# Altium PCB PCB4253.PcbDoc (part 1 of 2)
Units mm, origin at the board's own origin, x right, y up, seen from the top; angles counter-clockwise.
Board outline 30 x 51 mm, 6 copper layers (Top Layer, Signal Layer 2, GND Layer 3, PWR Layer 4, Signal Layer 5, Bottom Layer), stack 1.656 mm thick; 84 components, 108 nets, 396 pads, 436 vias.
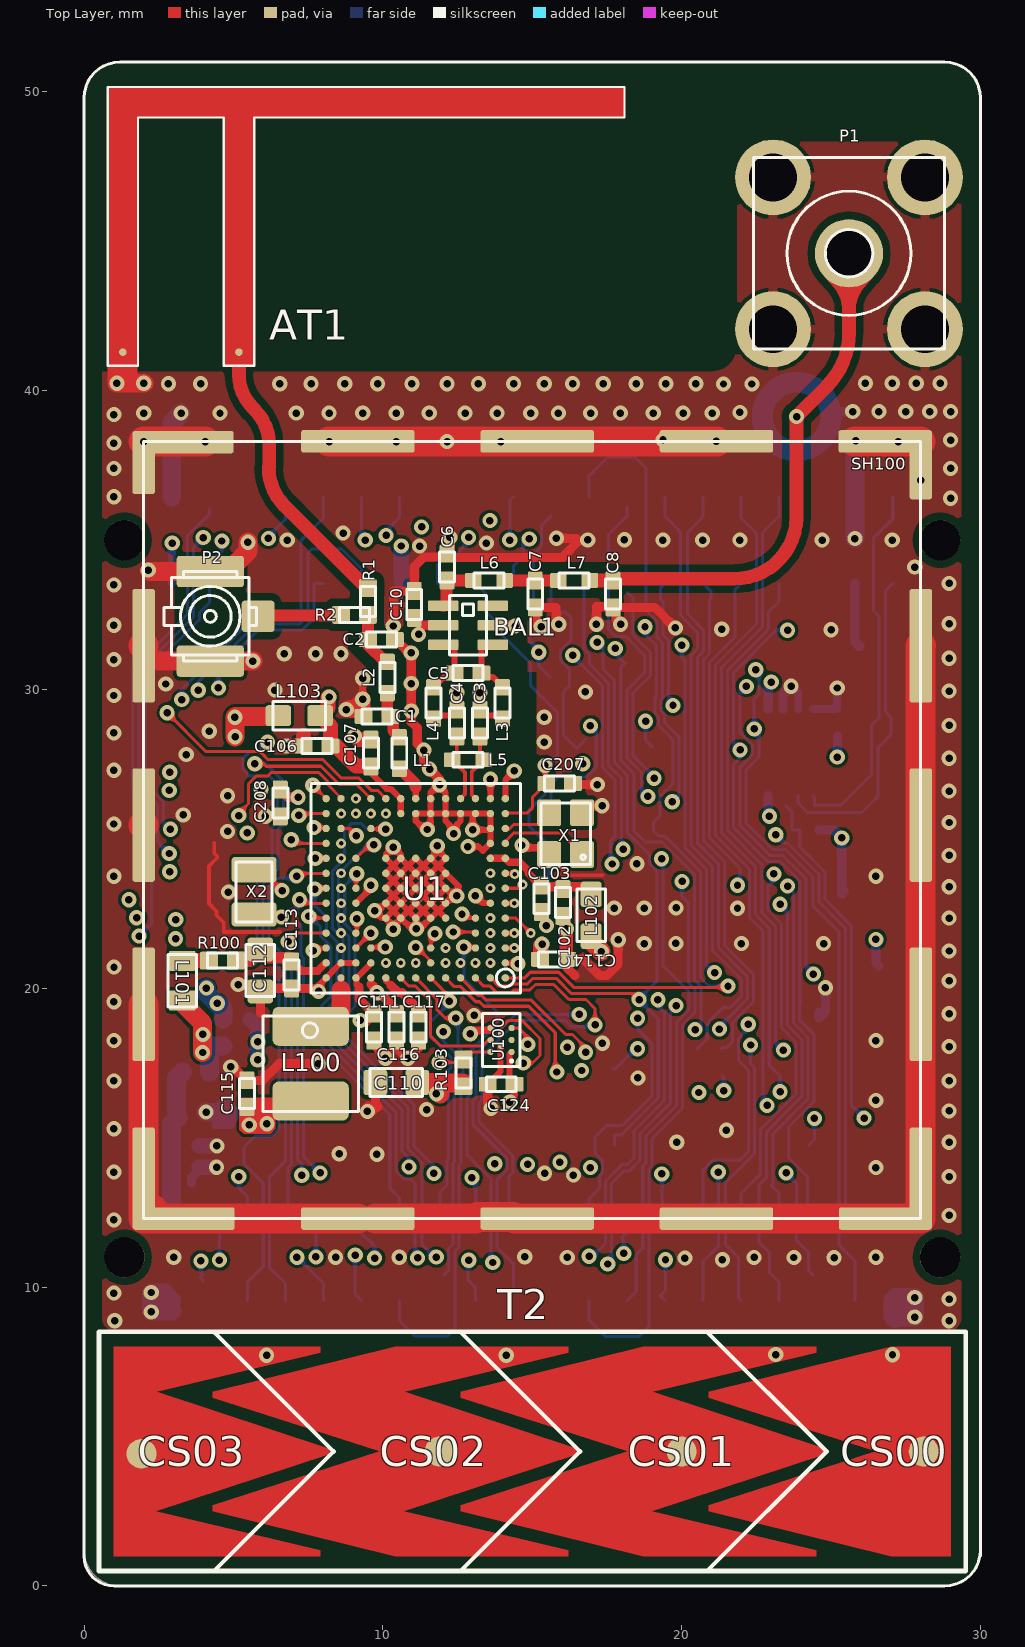
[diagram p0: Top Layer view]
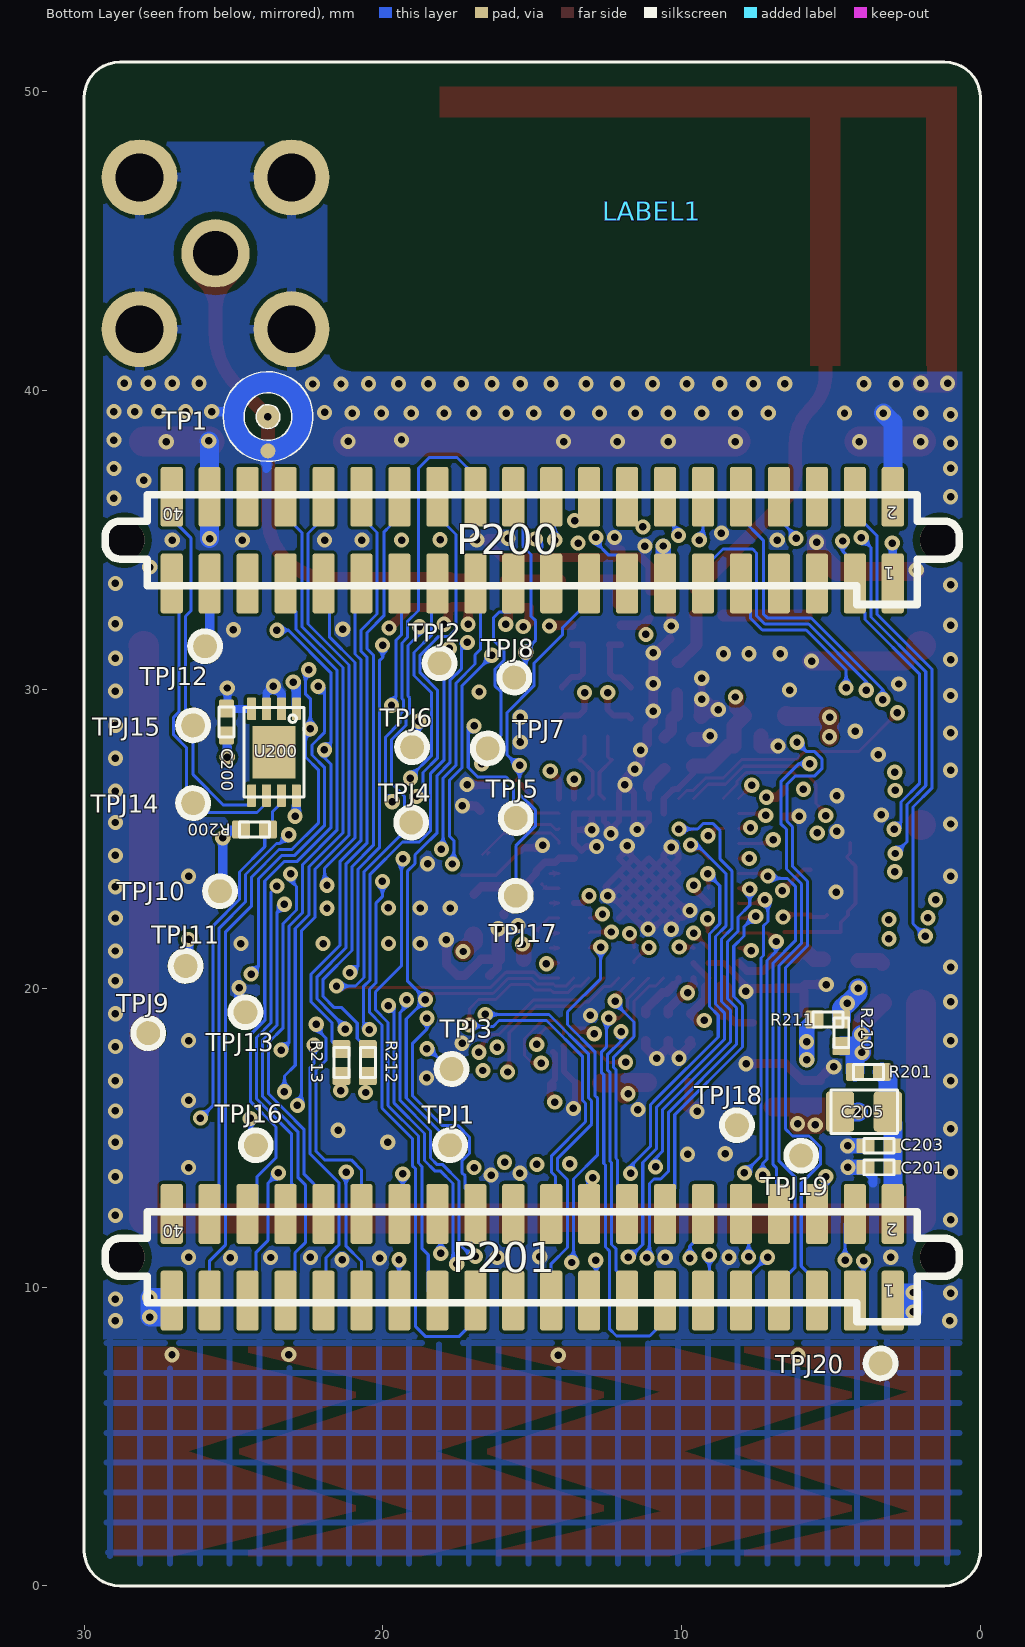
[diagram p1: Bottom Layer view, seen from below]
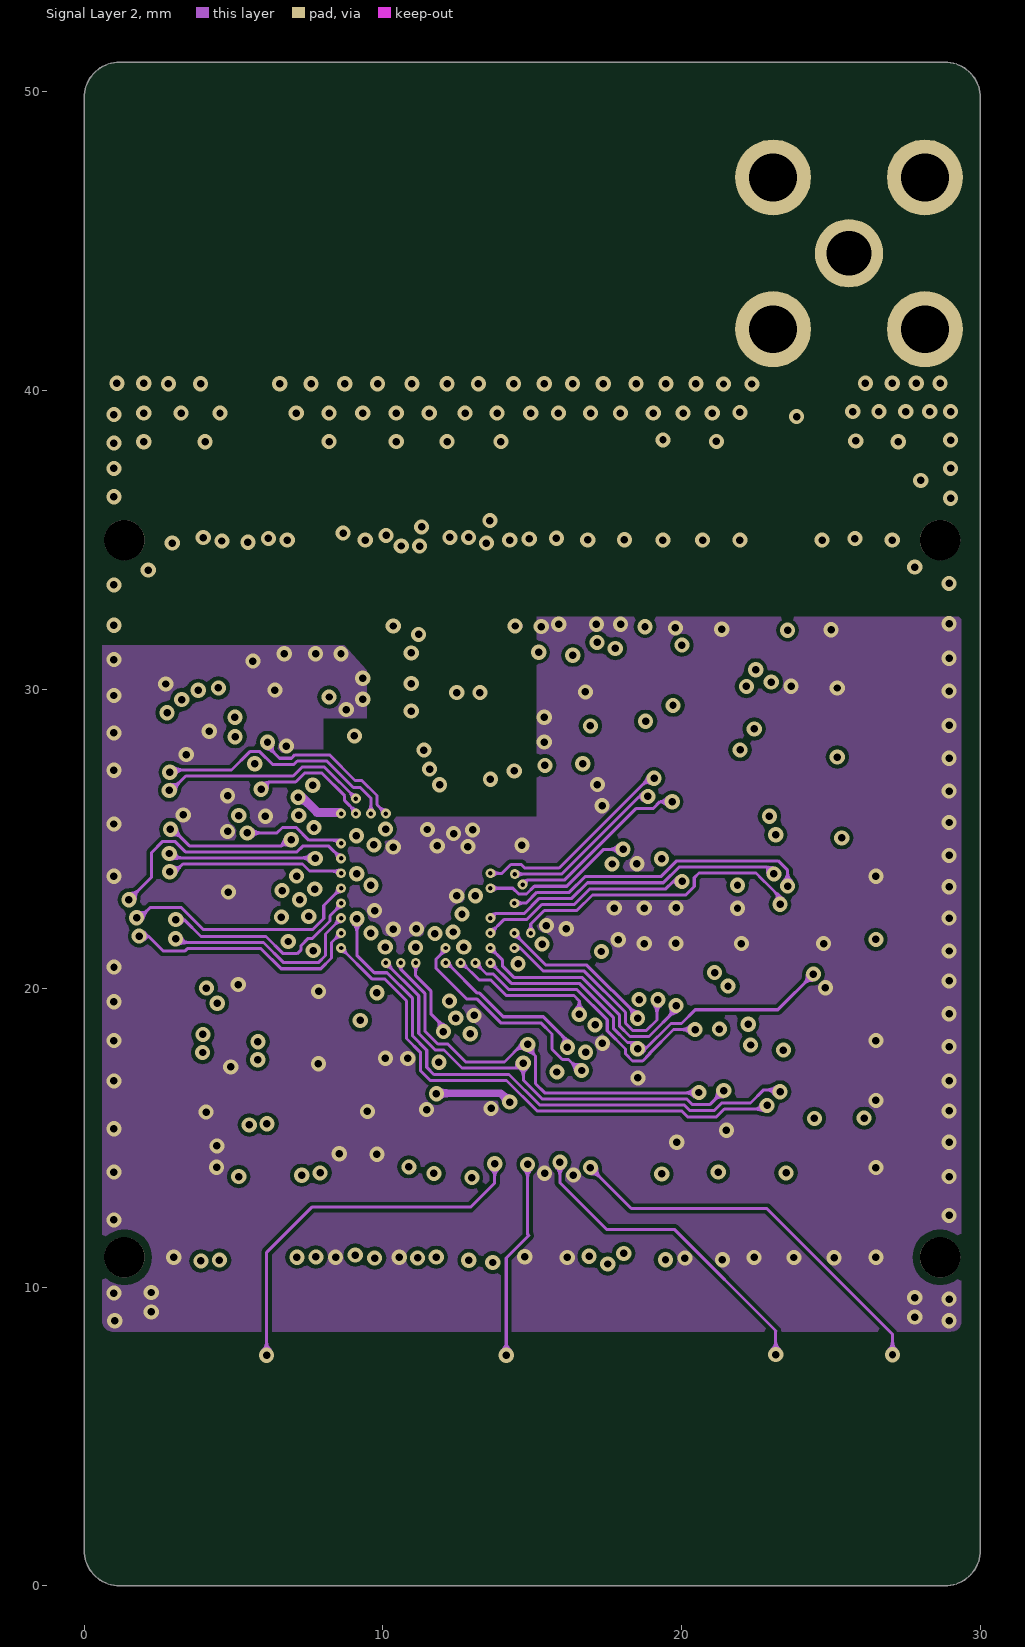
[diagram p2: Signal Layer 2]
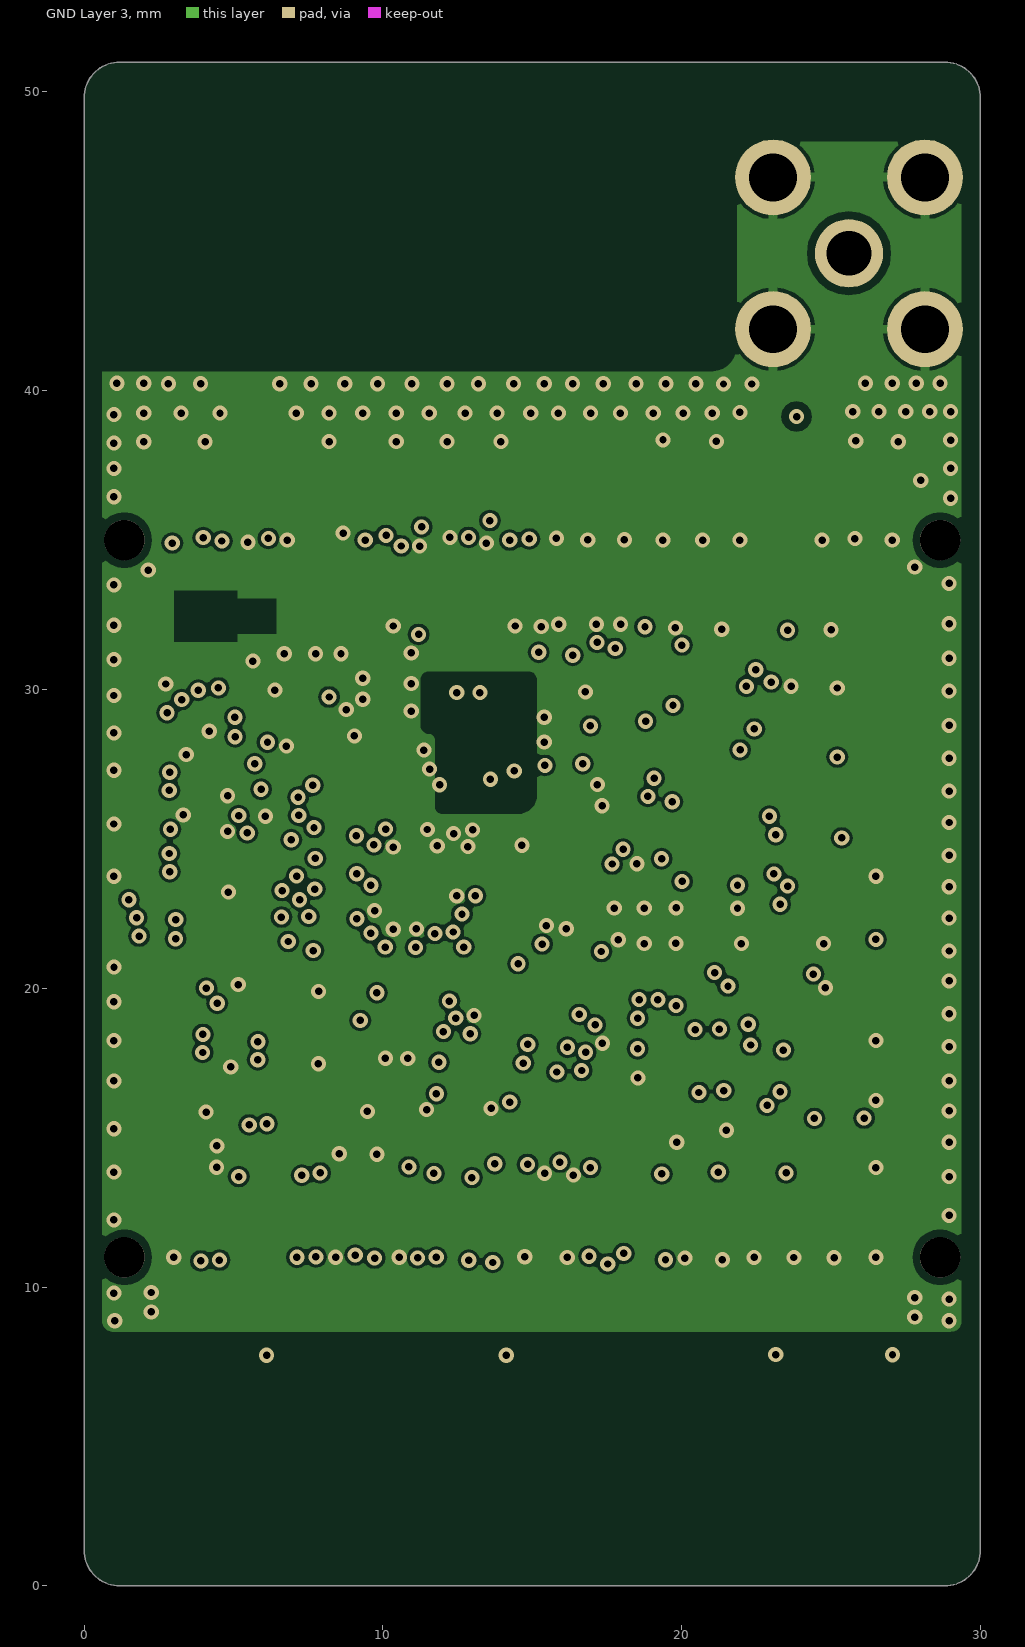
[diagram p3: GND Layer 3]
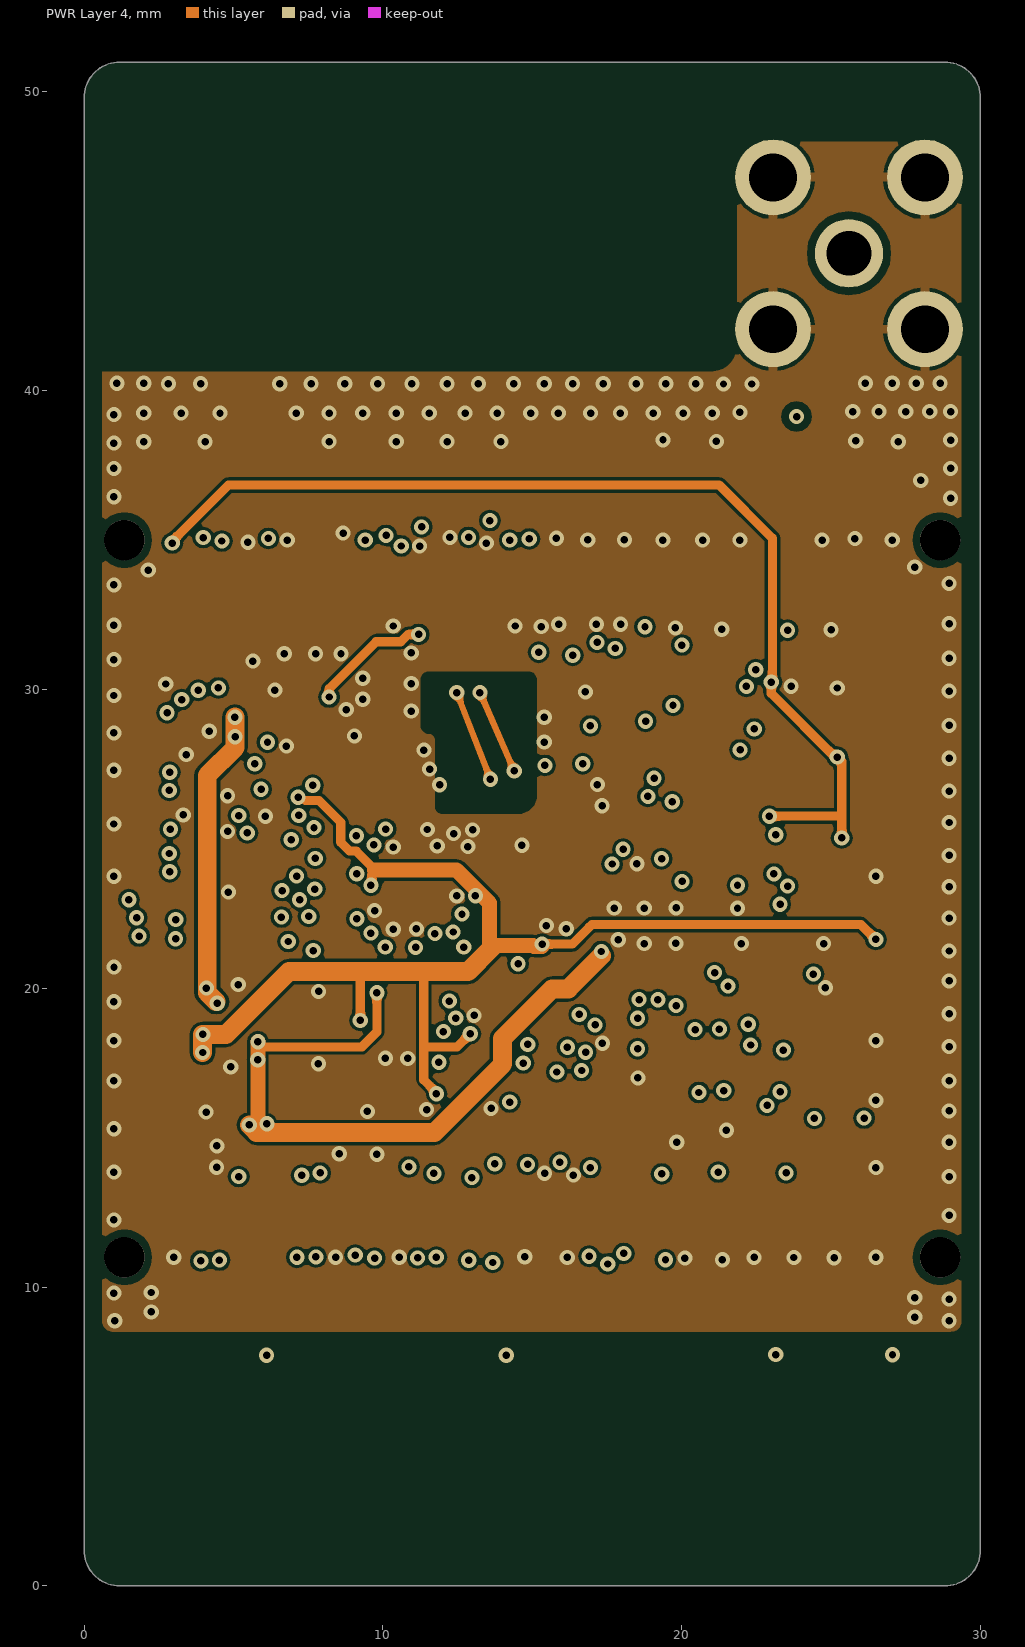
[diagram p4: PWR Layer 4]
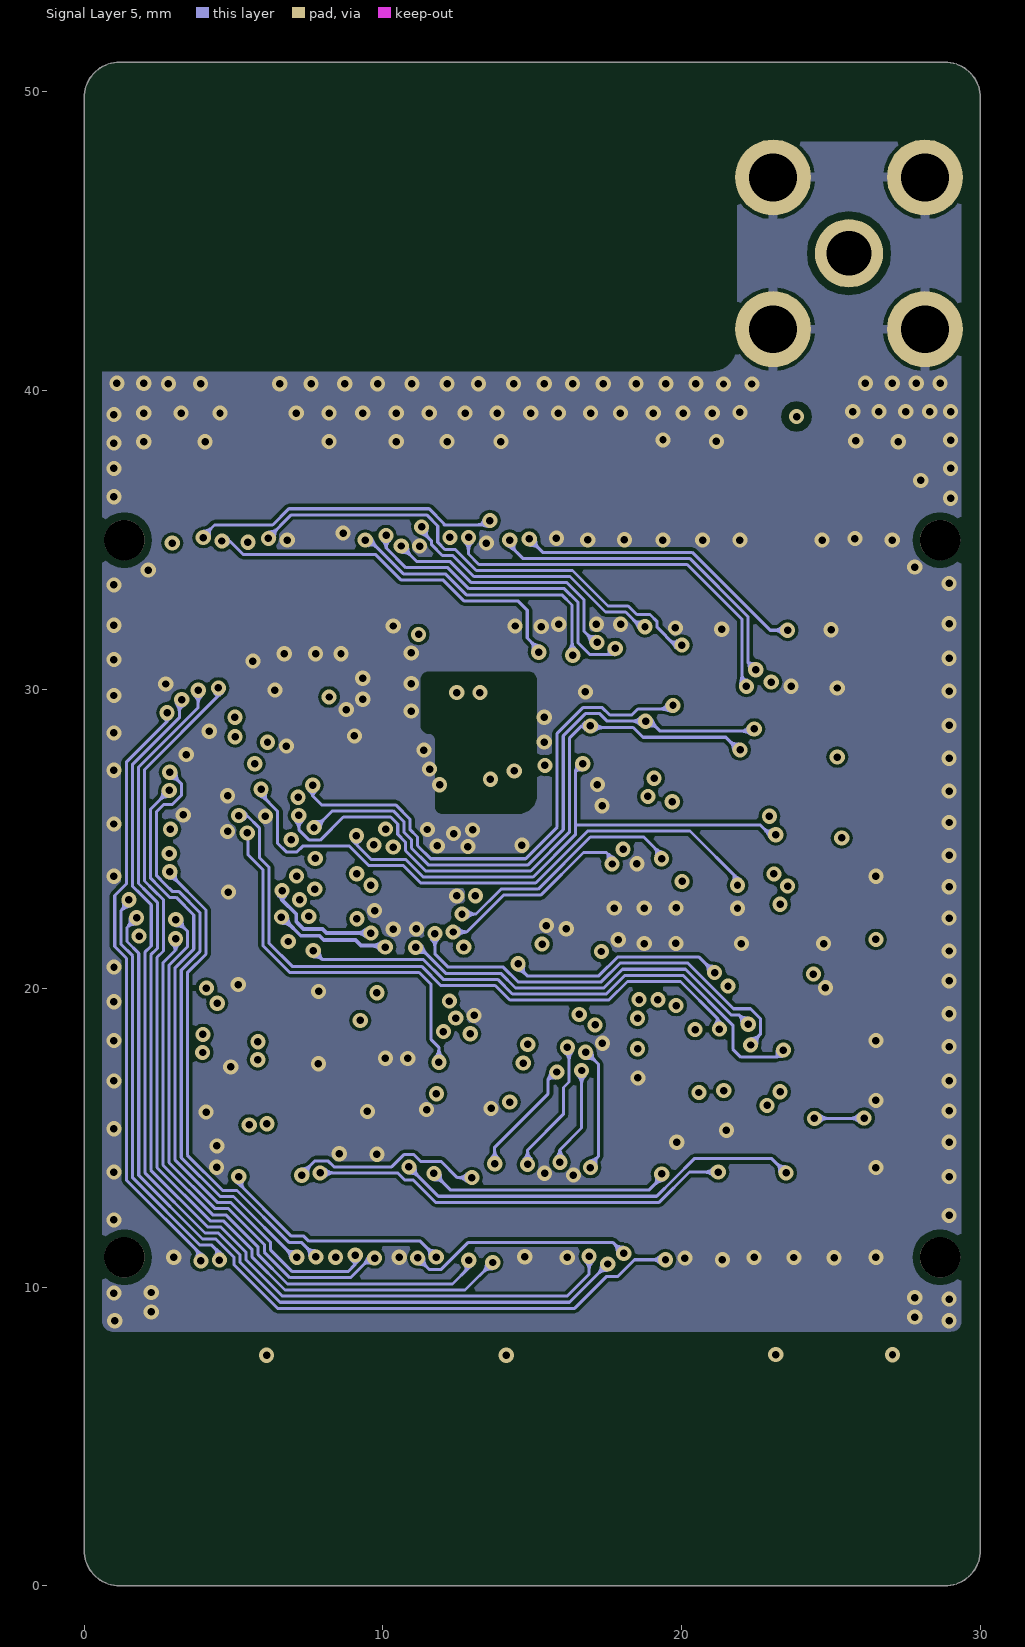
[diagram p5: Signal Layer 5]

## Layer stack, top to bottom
Top Solder: solder mask 0.01, Solder Resist, Dk 3.5
Top Layer: signal copper 0.035
Dielectric 1: prepreg 0.09, FR-4, Dk 4.2
Signal Layer 2: signal copper 0.035
Dielectric 2: core 0.18, Dk 4.2
GND Layer 3: signal copper 0.035
Dielectric 3: prepreg 0.906, FR-4, Dk 4.2
PWR Layer 4: signal copper 0.035
Dielectric 5: core 0.18, Dk 4.2
Signal Layer 5: signal copper 0.035
Dielectric 6: prepreg 0.09, Dk 4.2
Bottom Layer: signal copper 0.035
Bottom Solder: solder mask 0.01, Solder Resist, Dk 3.5

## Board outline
0,1.2 ccw(c1.2,1.2) 1.2,0 28.8,0 ccw(c28.8,1.2) 30,1.2 30,49.8 ccw(c28.8,49.8) 28.8,51 1.2,51 ccw(c1.2,49.8) 0,49.8

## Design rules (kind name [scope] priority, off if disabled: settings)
Clearance Clearance_to_Holes [InPadClass('NPTH')] p1: gap=0.254
Clearance Clearance_NetP2_1 [InNet('NetP2_1')] p2: gap=0.25
Clearance Clearance_NetC8 [InNet('NetC8_1')] p3: gap=0.25
Clearance Clearance_Net_AT1_1 [InNet('NetAT1_1')] p4: gap=0.25
Clearance Clerance_Polygon_GND3 [InNamedPolygon('GND_3')] p5: gap=0.127
Clearance Clerance_Polygon_GND2 [InNamedPolygon('GND_2')] p6: gap=0.127
Clearance Clerance_Polygon_GND1 [InNamedPolygon('GND_L2')] p7: gap=0.127
Clearance Clerance_Polygon_GND4 [InNamedPolygon('GND_4')] p8: gap=0.127
Clearance Clearance_General [All] p9: gap=0.102
HoleToHoleClearance HoleToHoleClearance_ANT1toPAD [Incomponent ('ANT1') vs ISpad] p1: gap=0 allowstackedmicrovias=TRUE
HoleToHoleClearance HoleToHoleClearance_U1toVIA_1 [InComponent ('U1') vs IsVia] p2: gap=0 allowstackedmicrovias=TRUE
HoleToHoleClearance [All] p3: gap=0.254 allowstackedmicrovias=TRUE
MinimumSolderMaskSliver [All] p1: minsoldermaskwidth=0.102
PolygonConnect PolygonConnect_SH100 [InComponent('SH100')] p1: connectstyle=Direct reliefconductorwidth=0.254 reliefentries=4 polygonreliefangle="90 Angle" airgapwidth=0.127
PolygonConnect PolygonConnect_P1 [InComponent('P1')] p2: connectstyle=Relief reliefconductorwidth=0.305 reliefentries=4 polygonreliefangle="90 Angle" airgapwidth=0.127
PolygonConnect Polygon_VIA_Connect [IsVia] p3: connectstyle=Direct reliefconductorwidth=0.254 reliefentries=4 polygonreliefangle="90 Angle" airgapwidth=0.254
PolygonConnect PolygonConnect_General [All] p4: connectstyle=NoConnect reliefconductorwidth=0.254 reliefentries=4 polygonreliefangle="90 Angle" airgapwidth=0.127
RoutingVias [All] p1: holewidth=0.25 width=0.508 viastyle="Through Hole" minholewidth=0.25 minwidth=0.508 maxholewidth=1 maxwidth=1.5
SilkToSilkClearance [All] p1: silktosilkclearance=0.102
SilkToSolderMaskClearance [IsPad] p1: minsilkscreentomaskgap=0.102 clearancetoexposedcopper=TRUE
SolderMaskExpansion [All] p1: expansion=0.051
Width [All] p1: maxlimit=5.08 minlimit=0.102 preferedwidth=0.127
26 further rules are at their usual default settings.

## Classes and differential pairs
pad class NPTH: P200-M1 P200-M2 P201-M1 P201-M2
net class RADIO_PK[2..0]: RADIO_PK0 RADIO_PK1 RADIO_PK2
net class RADIO_PJ[15..14]: RADIO_PJ14 RADIO_PJ15
net class RADIO_PI[3..0]: RADIO_PI0 RADIO_PI1 RADIO_PI2 RADIO_PI3
component class "01_ Title Page": PCB1
component class "02_ RF, Antenna & Power": AT1 BAL1 C1 C2 C3 C4 C5 C6 C7 C8 C10 C102 C103 C106 C107 C110 C111 C112 C113 C114 C115 C116 C117 C208 L1 L2 L3 L4 L5 L6 L7 L100 L101 L102 L103 P1 P2 R1 R2 R100 R210 R211 SH100 TP1 X1 X2
component class "03_ EFR32 Signal Assign": 180 C124 C207 R103 R203 R204 R213 RP200 T2 U1
component class "04_ WSTK Connectors & B": C200 C201 C203 C205 R200 R201 TPJ1 TPJ2 TPJ3 TPJ4 TPJ5 TPJ6 TPJ7 TPJ8 TPJ9 TPJ10 TPJ11 TPJ12 TPJ13 TPJ14 TPJ15 TPJ16 TPJ17 TPJ18 TPJ19 TPJ20 U200
net class RADIO_PA[9..0]: RADIO_PA0 RADIO_PA1 RADIO_PA2 RADIO_PA3 RADIO_PA4 RADIO_PA5 RADIO_PA6 RADIO_PA7 RADIO_PA8 RADIO_PA9
net class RADIO_PB[15..6]: RADIO_PB6 RADIO_PB7 RADIO_PB8 RADIO_PB9 RADIO_PB10 RADIO_PB11 RADIO_PB12 RADIO_PB13 RADIO_PB14 RADIO_PB15
net class RADIO_PC[11..0]: RADIO_PC0 RADIO_PC1 RADIO_PC2 RADIO_PC3 RADIO_PC4 RADIO_PC5 RADIO_PC6 RADIO_PC7 RADIO_PC8 RADIO_PC9 RADIO_PC10 RADIO_PC11
net class RADIO_PD[15..8]: RADIO_PD8 RADIO_PD9 RADIO_PD10 RADIO_PD11 RADIO_PD12 RADIO_PD13 RADIO_PD14 RADIO_PD15
net class RADIO_PF[15..0]: RADIO_PF0 RADIO_PF1 RADIO_PF2 RADIO_PF3 RADIO_PF4 RADIO_PF5 RADIO_PF6 RADIO_PF7 RADIO_PF8 RADIO_PF9 RADIO_PF10 RADIO_PF11 RADIO_PF12 RADIO_PF13 RADIO_PF14 RADIO_PF15
net class WSTK_F[21..0]: WSTK_F4 WSTK_F15 WSTK_F16
net class WSTK_P[45..0]: WSTK_P18 WSTK_P19 WSTK_P32 WSTK_P38 WSTK_P39 WSTK_P40

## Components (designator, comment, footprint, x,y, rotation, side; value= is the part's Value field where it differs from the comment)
AT1 "INVERTED_F" ANT_INV_F_2.4_GHZ_17.3MM_MIR 0.79,40.84 r0 top locked net-tie
BAL1 "0900BL15C050" BALUN_JOH_0900BL15 12.85,32.15 r0 top
C1 "cfg" C0402_L 9.8,29.1 r0 top
C2 "cfg" C0402_L 9.95,31.675 r180 top
C3 "cfg" C0402_L 13.25,28.875 r270 top
C4 "cfg" C0402_L 12.475,28.875 r270 top
C5 "cfg" C0402_L 12.85,30.55 r180 top
C6 "cfg" C0402_L 12.15,34.1 r90 top
C7 "cfg" C0402_L 15.1,33.2 r270 top
C8 "cfg" C0402_L 17.7,33.2 r270 top
C10 "cfg" C0402_L 11.05,32.85 r90 top
C102 "100P" C0402_L 16.03,22.869 r270 top
C103 "10P" C0402_L 15.306,22.998 r270 top
C106 "220N" C0402_L 7.793,28.107 r180 top
C107 "10P" C0402_L 9.6,27.875 r90 top
C110 "10U" C0603_L 10.45,16.85 r180 top
C111 "1U" C0402_L 9.7,18.7 r270 top
C112 "10U" C0603_L 5.9,20.6 r270 top
C113 "10N" C0402_L 6.95,20.45 r270 top
C114 "1U" C0402_L 15.711,20.972 r0 top
C115 "4U7" C0402_L 5.45,16.475 r90 top
C116 "100N" C0402_L 10.45,18.7 r270 top
C117 "1U" C0402_L 11.2,18.7 r270 top
C124 "100N" C0402_L 13.961,16.791 r180 top
C200 "100N" C0402_L 25.232,28.915 r90 bottom
C201 "100N" C0402_L 3.4,14.012 r0 bottom
C203 "100N" C0402_L 3.4,14.732 r0 bottom
C205 "10U" C0805_L 3.9,15.875 r0 bottom
C207 "100N" C0402_L 15.918,26.857 r0 top
C208 "100N" C0402_L 6.569,26.201 r270 top
L1 "cfg" COIL_0402_L 10.55,27.875 r90 top
L2 "cfg" COIL_0402_L 10.15,30.4 r90 top
L3 "cfg" COIL_0402_L 14,29.55 r270 top
L4 "cfg" COIL_0402_L 11.7,29.55 r270 top
L5 "cfg" COIL_0402_L 12.85,27.65 r0 top
L6 "cfg" COIL_0402_L 13.55,33.65 r180 top
L7 "cfg" COIL_0402_L 16.4,33.65 r180 top
L100 "4U7" COIL_MUR_LQH3NP_1212 7.584,17.477 r270 top
L101 "CBF102WB" COIL_WURTH_CBF_0603_L 3.286,20.257 r90 top
L102 "BLM18AG601SN1" COIL_MUR_BLM18_0603 16.972,22.446 r90 top
L103 "BLM18AG601SN1" COIL_MUR_BLM18_0603 7.2,29.125 r0 top
LABEL1 "Comment" LABEL_4CORNERS_19.0X6.0 11,46 r180 bottom
P1 "SMA" TE_SMA_1814832_TH_VER 25.6,44.6 r0 top locked
P2 "U.FL" COAX_HIROSE_U.FL_CL331-0471 4.225,32.45 r270 top
P200 "SOCKET_2X20_1.27MM_SMD" SAM_SFC-120-T2-D-A-2X20_SNUM 15,35 r0 bottom
P201 "SOCKET_2X20_1.27MM_SMD" SAM_SFC-120-T2-D-A-2X20_SNUM 15,11 r0 bottom
R1 "0R" R0402_L 9.5,32.95 r90 top
R2 "0R" R0402_L 9.05,32.5 r180 top
R100 "1R" R0402_L 4.631,20.926 r0 top
R103 "330K" R0402_L 12.695,17.172 r90 top
R200 "10K" R0402_L 24.295,25.314 r0 bottom
R201 "0R" R0402_L 3.75,17.2 r0 bottom
R210 "0R" R0402_L 4.658,18.516 r270 bottom
R211 "0R" R0402_L 5.108,18.955 r0 bottom
R212 "100R" R0402_L 20.504,17.516 r90 bottom
R213 "100R" R0402_L 21.39,17.52 r90 bottom
SH100 "RF_SHIELD_FRAME_BMI-S-203-F" RF_SHIELD_FRAME_BMI-S-203-F_PCB4100 15,25.3 r0 top locked
T2 "TOUCH SLIDER" TOUCH_SLIDER2_28.0X7.0-4 0.5,0.5 r0 top
TP1 "RF_TEST_POINT" TP_INGUN_50_OHM_CLOSED 23.845,39.135 r180 bottom
TPJ1 "TPJ_SMD" TP_1.0_SMD 17.75,14.75 r90 bottom
TPJ2 "TPJ_SMD" TP_1.0_SMD 18.1,30.88 r90 bottom
TPJ3 "TPJ_SMD" TP_1.0_SMD 17.7,17.3 r90 bottom
TPJ4 "TPJ_SMD" TP_1.0_SMD 19.05,25.55 r90 bottom
TPJ5 "TPJ_SMD" TP_1.0_SMD 15.55,25.7 r90 bottom
TPJ6 "TPJ_SMD" TP_1.0_SMD 19.02,28.07 r90 bottom
TPJ7 "TPJ_SMD" TP_1.0_SMD 16.49,28.03 r90 bottom
TPJ8 "TPJ_SMD" TP_1.0_SMD 15.6,30.4 r90 bottom
TPJ9 "TPJ_SMD" TP_1.0_SMD 27.85,18.5 r90 bottom
TPJ10 "TPJ_SMD" TP_1.0_SMD 25.45,23.25 r90 bottom
TPJ11 "TPJ_SMD" TP_1.0_SMD 26.6,20.75 r90 bottom
TPJ12 "TPJ_SMD" TP_1.0_SMD 25.95,31.45 r90 bottom
TPJ13 "TPJ_SMD" TP_1.0_SMD 24.6,19.2 r90 bottom
TPJ14 "TPJ_SMD" TP_1.0_SMD 26.35,26.2 r90 bottom
TPJ15 "TPJ_SMD" TP_1.0_SMD 26.35,28.8 r90 bottom
TPJ16 "TPJ_SMD" TP_1.0_SMD 24.25,14.75 r90 bottom
TPJ17 "TPJ_SMD" TP_1.0_SMD 15.55,23.1 r90 bottom
TPJ18 "TPJ_SMD" TP_1.0_SMD 8.15,15.42 r90 bottom
TPJ19 "TPJ_SMD" TP_1.0_SMD 6,14.4 r90 bottom
TPJ20 "TPJ_SMD" TP_1.0_SMD 3.34,7.45 r90 bottom
U1 "EFR32MG2_BGA125_0A" BGA125_M050_7.0X7.0 11.1,23.35 r180 top
U100 "MX25R8035F" BGA8_M040_1.24x1.75_WLCSP 13.958,18.271 r180 top
U200 "24AA024" TDFN8_M050_2.0X3.0_EP 23.642,27.901 r270 bottom
X1 "38.400 MHz" X_SSS_DSX211SH_2.05X1.65-4 16.117,25.177 r90 top
X2 "32.768kHz" X_MCS_CM8V-T1A 5.692,23.224 r90 top

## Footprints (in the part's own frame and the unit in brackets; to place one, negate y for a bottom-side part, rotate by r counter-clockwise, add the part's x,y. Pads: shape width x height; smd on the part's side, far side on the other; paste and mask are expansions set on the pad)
ANT_INV_F_2.4_GHZ_17.3MM_MIR [mil] "Antenna inverted F, 2.4 GHz, 17.3 mm (MIR)"
  round 10 smd paste-5 mask-5: 1(173,17.72) 2(20.01,17.72)
  Top Layer region: 0.36,367.2 681,367.2 681,327.07 193.36,327.07 193.36,0 153.36,0 153.36,327.07 40.36,327.07 40.36,0 20.36,0 0.36,0
  silkscreen extent 0,0 681,367
BALUN_JOH_0900BL15 [mil] "BALUN JOHANSON 0900BL15 0805"
  rrect20% 40x14 smd: 1(-32.5,25.59) 2(-32.5,0) 3(-32.5,-25.59) 4(32.5,-25.59) 5(32.5,0) 6(32.5,25.59)
  silkscreen extent -25,-39 25,39, body extent -27,-41 27,41, height 32
BGA8_M040_1.24x1.75_WLCSP [mm] "BGA, 8 pin. U100"
  round 0.21 smd mask+0.051: A1(-0.35,0.4) A3(0.35,0.4) B2(0,0.2) C1(-0.35,0) C3(0.35,0) D2(0,-0.2) E1(-0.35,-0.4) E3(0.35,-0.4)
  silkscreen extent -0.63,-0.89 0.63,0.88, body extent -0.63,-0.89 0.63,0.88, height 0.52
BGA125_M050_7.0X7.0 [mm] "(BGA125N7X7P0.5)"
  round 0.25 smd: A1(-3,3) A2(-2.5,3) A3(-2,3) A4(-1.5,3) A5(-1,3) A6(-0.5,3) A7(0,3) A8(0.5,3) A9(1,3) A10(1.5,3) A11(2,3) A12(2.5,3) A13(3,3) B1(-3,2.5) B2(-2.5,2.5) B3(-2,2.5) B4(-1.5,2.5) B5(-1,2.5) B6(-0.5,2.5) B7(0,2.5) B8(0.5,2.5) B9(1,2.5) B10(1.5,2.5) B11(2,2.5) B12(2.5,2.5) B13(3,2.5) C1(-3,2) C2(-2.5,2) C3(-2,2) C5(-1,2) C6(-0.5,2) C10(1.5,2) C11(2,2) C12(2.5,2) C13(3,2) D1(-3,1.5) D2(-2.5,1.5) D3(-2,1.5) D11(2,1.5) D12(2.5,1.5) D13(3,1.5) E1(-3,1) E2(-2.5,1) E3(-2,1) E5(-1,1) E6(-0.5,1) E7(0,1) E8(0.5,1) E9(1,1) E12(2.5,1) E13(3,1) F1(-3,0.5) F2(-2.5,0.5) F5(-1,0.5) F6(-0.5,0.5) F7(0,0.5) F8(0.5,0.5) F9(1,0.5) F11(2,0.5) F12(2.5,0.5) F13(3,0.5) G1(-3,0) G2(-2.5,0) G5(-1,0) G6(-0.5,0) G7(0,0) G8(0.5,0) G9(1,0) G11(2,0) G12(2.5,0) G13(3,0) H1(-3,-0.5) H2(-2.5,-0.5) H5(-1,-0.5) H6(-0.5,-0.5) H7(0,-0.5) H8(0.5,-0.5) H9(1,-0.5) H12(2.5,-0.5) H13(3,-0.5) J1(-3,-1) J2(-2.5,-1) J5(-1,-1) J6(-0.5,-1) J7(0,-1) J8(0.5,-1) J9(1,-1) J11(2,-1) J12(2.5,-1) J13(3,-1) K1(-3,-1.5) K2(-2.5,-1.5) K12(2.5,-1.5) K13(3,-1.5) L1(-3,-2) L2(-2.5,-2) L10(1.5,-2) L12(2.5,-2) L13(3,-2) M1(-3,-2.5) M2(-2.5,-2.5) M3(-2,-2.5) M4(-1.5,-2.5) M5(-1,-2.5) M6(-0.5,-2.5) M7(0,-2.5) M8(0.5,-2.5) M9(1,-2.5) M10(1.5,-2.5) M11(2,-2.5) M12(2.5,-2.5) M13(3,-2.5) N1(-3,-3) N2(-2.5,-3) N3(-2,-3) N4(-1.5,-3) N5(-1,-3) N6(-0.5,-3) N7(0,-3) N8(0.5,-3) N9(1,-3) N10(1.5,-3) N11(2,-3) N12(2.5,-3) N13(3,-3)
  silkscreen extent -3.5,-3.5 3.5,3.5, body extent -3.5,-3.5 3.5,3.5, height 1.01
C0402_L [mm] "Chip Capacitor, 2-Leads, Body 1.0x0.5mm, IPC High Density"
  rrect20% 0.6x0.5 smd mask+0.051: 1(-0.45,0) 2(0.45,0)
  silkscreen extent -0.5,-0.25 0.5,0.25, body extent -0.5,-0.25 0.5,0.25, height 0.6
C0603_L [mm] "Capacitor, 0603, High Density (C)"
  rrect25% 0.8x0.85 smd: 1(-0.7,0) 2(0.7,0)
  silkscreen extent -0.88,-0.48 0.87,0.48, body extent -0.88,-0.48 0.87,0.48, height 0.95
C0805_L [mm] "Capacitor, 0805"
  rrect25% 0.95x1.35 smd: 1(-0.8,0) 2(0.8,0)
  silkscreen extent -1.12,-0.72 1.1,0.72, body extent -1.1,-0.72 1.1,0.72, height 1.45
COAX_HIROSE_U.FL_CL331-0471 [mm] "COAX_HIROSE_U.FL_CL331-0471"
  rrect20% 1.05x1.1 smd mask+0.051: 1(0,1.6)
  rrect20% 1.05x2.25 smd mask+0.051: 2(-1.5,0) 3(1.5,0)
  Top Layer pour cut-out: -0.85,0.9 0.85,0.9 0.85,0.9 0.85,-1.2 -0.85,-1.2 -0.85,-1.2
  silkscreen extent -1.5,-1.55 1.5,1.55, body extent -1.3,-1.55 1.3,1.3, height 0.9
COIL_0402_L [mm] "COIL_0402_L"
  rrect20% 0.55x0.5 smd mask+0.051: 1(-0.525,0) 2(0.525,0)
  silkscreen extent -0.5,-0.25 0.5,0.25, body extent -0.5,-0.25 0.5,0.25, height 0.6
COIL_MUR_BLM18_0603 [mm] "COIL_MUR_BLM18P_0603"
  rrect25% 0.85x0.7 smd mask+0.051: 1(-0.7,0) 2(0.7,0)
  silkscreen extent -0.88,-0.48 0.87,0.48, body extent -0.88,-0.48 0.87,0.48, height 0.95
COIL_MUR_LQH3NP_1212 [mm] "COIL_MUR_LQH3NP_1212"
  rrect30% 1.3x2.55 smd mask+0.051: 1(-1.25,0) 2(1.25,0)
  silkscreen extent -1.6,-1.6 1.6,1.6, body extent -1.6,-1.6 1.6,1.6, height 1.5
COIL_WURTH_CBF_0603_L [mm] "COIL_WURTH_CBF_0603_L (= L0603_0.8_L)"
  rrect10% 0.67x0.88 smd: 1(-0.665,0) 2(0.665,0)
  silkscreen extent -0.87,-0.48 0.87,0.48, body extent -0.87,-0.48 0.87,0.48, height 0.95
LABEL_4CORNERS_19.0X6.0 [mm]
R0402_L [mm] "Chip Resistor, 2-Leads, Body 1.0x0.5mm, IPC High Density"
  rrect20% 0.6x0.6 smd mask+0.051: 1(-0.45,0) 2(0.45,0)
  silkscreen extent -0.5,-0.25 0.5,0.25, body extent -0.5,-0.25 0.5,0.25, height 0.6
RF_SHIELD_FRAME_BMI-S-203-F_PCB4100 [mm] "RF_SHIELD_FRAME_BMI-S-203-F"
  rrect20% 0.75x3.8 smd paste+0 mask+0.05: 1(-13.005,-5.835) 1(-13.005,0.165) 1(-13.005,6.165) 1(13.005,-5.835) 1(13.005,0.165) 1(13.005,6.165)
  rrect20% 0.75x3.4 smd paste+0 mask+0.05: 1(-13.005,-11.659) 1(13.005,-11.659)
  rrect20% 0.75x2.1 smd paste+0 mask+0.05: 1(-13.005,12.294)
  oval 0.75x0.254 smd paste+0 mask+0.05: 1(-13.004,12.994) 1(12.994,12.994) 1(12.994,12.994) 1(12.994,12.994)
  rrect20% 3.375x0.75 smd paste+0 mask+0.05: 1(-11.684,12.979)
  rrect20% 3.4x0.75 smd paste+0 mask+0.05: 1(-11.659,-13.005)
  rrect20% 3.8x0.75 smd paste+0 mask+0.05: 1(-5.835,-13.005) 1(-5.835,13.005) 1(0.165,-13.005) 1(0.165,13.005) 1(6.165,-13.005) 1(6.165,13.005)
  rrect20% 3.1x0.75 smd paste+0 mask+0.05: 1(11.811,-13.005)
  rrect20% 3.125x0.75 smd paste+0 mask+0.05: 1(11.811,13.005)
  rrect20% 0.75x2.3 smd paste+0 mask+0.05: 1(13.005,12.217)
  silkscreen extent -13.01,-13.01 13,13, body extent -13,-13 12.99,12.99, height 5.08
SAM_SFC-120-T2-D-A-2X20_SNUM [mm]
  rrect20% 0.74x2 smd mask+0.05: 1(-12.065,1.45) 2(-12.065,-1.45) 3(-10.795,1.45) 4(-10.795,-1.45) 5(-9.525,1.45) 6(-9.525,-1.45) 7(-8.255,1.45) 8(-8.255,-1.45) 9(-6.985,1.45) 10(-6.985,-1.45) 11(-5.715,1.45) 12(-5.715,-1.45) 13(-4.445,1.45) 14(-4.445,-1.45) 15(-3.175,1.45) 16(-3.175,-1.45) 17(-1.905,1.45) 18(-1.905,-1.45) 19(-0.635,1.45) 20(-0.635,-1.45) 21(0.635,1.45) 22(0.635,-1.45) 23(1.905,1.45) 24(1.905,-1.45) 25(3.175,1.45) 26(3.175,-1.45) 27(4.445,1.45) 28(4.445,-1.45) 29(5.715,1.45) 30(5.715,-1.45) 31(6.985,1.45) 32(6.985,-1.45) 33(8.255,1.45) 34(8.255,-1.45) 35(9.525,1.45) 36(9.525,-1.45) 37(10.795,1.45) 38(10.795,-1.45) 39(12.065,1.45) 40(12.065,-1.45)
  round 1.35 hole 1.35 unplated paste-5.563 mask-5.563: M1(13.652,0) M2(-13.652,0)
  silkscreen extent -14.29,-1.53 14.29,2.15, body extent -14.65,-1.58 14.65,2.25, height 4.57
TDFN8_M050_2.0X3.0_EP [mm] "TDFN8_M050_2.0x3.0_EP"
  rrect20% 0.75x0.3 smd mask+0.051: 1(-1.45,0.75) 2(-1.45,0.25) 3(-1.45,-0.25) 4(-1.45,-0.75) 5(1.45,-0.75) 6(1.45,-0.25) 7(1.45,0.25) 8(1.45,0.75)
  rect 1.75x1.45 smd mask+0.051: 9(0,0)
  silkscreen extent -1.5,-1 1.5,1, body extent -1.5,-1 1.5,1, height 1.01
TE_SMA_1814832_TH_VER [mm]
  round 2.286 hole 1.5: 1(0,0)
  round 2.54 hole 1.6: 2(-2.54,-2.54) 3(2.54,-2.54) 4(2.54,2.54) 5(-2.54,2.54)
  silkscreen extent -3.2,-3.2 3.2,3.2, body extent -3.2,-3.2 3.2,3.2, height 9.5
TOUCH_SLIDER2_28.0X7.0-4 [mm]
  round 1 smd paste-0.51 mask-0.51: 1(1.424,3.924) 2(11.4,4) 3(19.5,4) 4(27.6,4)
  Top Layer region: 7.4,7.5 1.6,7.5 0.5,7.5 0.5,4 0.5,0.5 1.6,0.5 7.4,0.5 7.4,0.7 1.9,2 7.7,3.9 7.7,4.1 1.938,6 7.4,7.3
  Top Layer region: 15.7,7.5 9.9,7.5 3.8,6 3.8,5.8 9.4,4 3.8,2.2 3.8,2 9.9,0.5 15.7,0.5 15.7,0.7 10.2,2 16,3.9 16,4.1 10.238,6 15.7,7.3
  Top Layer region: 24,7.5 18.2,7.5 12.1,6 12.1,5.8 17.7,4 12.1,2.2 12.1,2 18.2,0.5 24,0.5 24,0.7 18.5,2 24.3,3.9 24.3,4.1 18.538,6 24,7.3
  Top Layer region: 28.5,7.5 26.5,7.5 20.4,6 20.4,5.8 26,4 20.4,2.2 20.4,2 26.5,0.5 28.5,0.5 28.5,2
  silkscreen extent 0,0 29,8
TP_1.0_SMD [mm] "Test Point, 1.0 mm, SMD"
  round 1 smd paste-0.501: 1(0,0)
  silkscreen extent -0.5,-0.5 0.5,0.5
TP_INGUN_50_OHM_CLOSED [mm] "TP_INGUN_50_OHM_CLOSED"
  round 0.8 smd paste-1.6 mask+1.11: 1(0,0)
  round 0.5 smd paste-0.255 mask-0.41: 2(0,-1.15)
  Top Layer lines w0.7: 0,-1.15 ccw(c0,0) -1.15,0 ccw(c0,0) 0,-1.15
  silkscreen extent -1.5,-1.5 1.5,1.5
X_MCS_CM8V-T1A [mm] "Crystal MCS CM8V-T1A (2 pin)"
  rrect25% 0.8x1.5 smd mask+0.051: 1(-0.75,0)
  rrect25% 0.85x1.5 smd mask+0.051: 2(0.75,0)
  silkscreen extent -1,-0.6 1,0.6, body extent -1,-0.6 1,0.6, height 0.97
X_SSS_DSX211SH_2.05X1.65-4 [mm] "X_SSS_DSX211SH_2.05X1.65-4"
  rrect20% 0.9x0.8 smd mask+0.051: 1(-0.7,-0.55) 2(0.7,-0.55) 3(0.7,0.55) 4(-0.7,0.55)
  silkscreen extent -1.02,-0.82 1.02,0.82, body extent -1.07,-0.87 1.07,0.87, height 0.51

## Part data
AT1: library part ANT_INVERTED_F
C1 C2 C3 C4 C5 C6 C7 C8 C10 C102 C103 C106 C107 C111 C113 C114 C115 C116 C117 C124 C200 C201 C203 C207 C208: library part C0402
C110 C112: library part C0603
C205: library part C0805
L1 L2 L3 L4 L5 L6 L7: library part L0402
L100: library part LQH3NP
L102 L103: library part BLM18AG
P1: library part SMA_TH
P2: library part HIROSE_U.FL
R1 R2 R100 R103 R200 R201 R210 R211 R212 R213: library part R0402
T2: library part TOUCH_SLIDER
TP1: library part TP_RF
U100: library part MX25R8035
X1: library part DSX211SH
X2: library part CM8V-T1A

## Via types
v1: diameter 0.508, hole 0.25, Top Layer to Bottom Layer, tented both sides, 404 vias
v2: diameter 0.33/0.33 (per signal layer), hole 0.15, Top Layer to Signal Layer 2, tented both sides, 31 vias
v3: diameter 0.33/0.33 (per signal layer), hole 0.15, Top Layer to Signal Layer 2, tented top, 1 vias

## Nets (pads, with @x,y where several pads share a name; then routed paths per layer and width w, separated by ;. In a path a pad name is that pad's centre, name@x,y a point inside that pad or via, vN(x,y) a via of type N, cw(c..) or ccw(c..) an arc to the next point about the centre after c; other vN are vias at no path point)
3V3: C200.1 P200.1 R200.2 TPJ10.1 U200.1 U200.8 | length 42.2
  PWR Layer 4 w0.305: v1(2.95,34.9) 2.95,34.964 4.836,36.85 21.25,36.85 23.038,35.062 23.038,30.212 v1(23,30.25) 23,29.874 25.133,27.74 v1(25.209,27.74) 25.359,27.591 25.359,25.751 ; v1(22.936,25.761) 25.304,25.761 25.336,25.729 25.359,25.751 ; v1(25.359,25.036) 25.359,25.751
  Bottom Layer w0.254: P200.1@2.935,33.55 2.935,34.885 v1(2.95,34.9)
  Bottom Layer w0.305: U200.8@22.892,26.451 22.892,25.729 22.924,25.761 v1(22.936,25.761) ; U200.1@22.892,29.351 22.898,29.357 22.898,30.148 v1(23,30.25) ; U200.1@22.893,29.365 22.894,29.366 U200.1@22.894,29.685 ; R200.2@24.6,25.3 25.095,25.3 v1(25.359,25.036) 25.359,23.159 TPJ10.1@25.45,23.25 ; v1(25.209,27.74) C200.1@25.209,28.441
5V: P200.37 TPJ12.1 | length 2.2
  Bottom Layer w0.33: P200.37@25.795,33.55 25.795,31.605 TPJ12.1@25.95,31.45
BOARD_ID_SCL: P200.39 TPJ14.1 U200.6 | length 10.8
  Bottom Layer w0.102: U200.6@23.892,26.451 23.892,26.203 24.21,25.885 26.035,25.885 TPJ14.1@26.35,26.2 26.565,26.415 26.565,28.046 27.002,28.484 27.002,29.07 26.819,29.254 26.819,33.304 P200.39@27.065,33.55
BOARD_ID_SDA: P200.40 TPJ15.1 U200.5 | length 12.4
  Bottom Layer w0.102: U200.5@24.392,26.451 24.442,26.402 U200.5@24.442,26.13 ; U200.5@24.442,26.119 U200.5@24.442,26.13 ; P200.40@27.065,36.45 27.065,35.715 26.425,35.075 26.425,32.626 26.602,32.449 26.602,29.052 TPJ15.1@26.35,28.8 26.35,27.149 25.331,26.13 U200.5@24.442,26.13
BOARD_ID_WP: R200.1 TPJ16.1 U200.7 | length 14.3
  Signal Layer 5 w0.102: v1(24.44,15.649) 25.963,15.649 25.971,15.657 v1(26.106,15.657)
  Bottom Layer w0.102: U200.7@23.497,26.101 23.7,25.898 23.7,25.3 23.952,25.3 23.952,24.743 24.798,23.897 24.798,22.98 25.679,22.098 25.679,16.084 v1(26.106,15.657) ; TPJ16.1@24.25,14.75 24.44,14.94 v1(24.44,15.649)
GND: AT1.2 BAL1.5 C1.1 C2.1 C6.2 C7.2 C8.2 C10.2 C102.2 C103.2 C106.2 C107.2 C110.2 C111.2 C112.2 C113.2 C114.2 C115.2 C116.2 C117.2 C124.2 C200.2 C201.2 C203.2 C205.2 C207.2 C208.2 P1.2 P1.3 P1.4 P1.5 P2.2 P2.3 P200.2 P200.38 P201.1 P201.39 SH100.1 TP1.2 TPJ13.1 U1.A13 U1.B11 U1.B12 U1.E5 U1.E6 U1.E7 U1.E8 U1.E9 U1.F5 U1.F6 U1.F7 U1.F8 U1.F9 U1.G5 U1.G6 U1.G7 U1.G8 U1.G9 U1.H5 U1.H6 U1.H7 U1.H8 U1.H9 U1.J5 U1.J6 U1.J7 U1.J8 U1.J9 U1.K2 U1.L2 U1.M2 U1.M3 U1.M4 U1.M5 U1.M6 U1.M7 U1.N5 U1.N6 U100.B2 U200.2 U200.3 U200.4 X1.2 X1.4 | length 202
  Top Layer w0.127: 4.356,24.868 4.356,24.521 4.458,24.419 4.458,24.368 4.178,24.089 4.178,22.836 4.432,22.582 4.432,22.444 4.676,22.201 4.676,21.885 6.56,21.885 ; v1@6.016,25.761 v1(6.071,25.761) ; C1.1@9.35,29.1 C1.1@9.4,29.1 ; X1.4@15.4,24.6 16.213,23.787 17.353,23.787
  Top Layer w0.203: v1(7.85,19.896) 7.85,20.1 U1.A13@8.1,20.35 U1.B12@8.6,20.85 U1.B11@9.1,20.85 ; v1(9.325,29.675) v1(9.325,30.375) ; v1(10.35,21.975) v1@10.35,22.1 ; v1(11.823,24.768) 11.917,24.768 11.954,24.731 11.836,24.614 v1@11.85,24.6 ; U1.E5@12.1,22.35 11.85,22.6 ; v1(12.849,24.746) 13.204,24.746 13.35,24.6 U1.K2@13.6,24.85 U1.L2@13.6,25.35 ; C124.2@13.511,16.791 13.939,17.218 13.939,18.052 U100.B2@13.958,18.071 ; U1.E9@10.1,22.35 v1@10.35,22.1 ; U1.E9@10.1,22.35 10.35,22.6 ; U1.E9@10.1,22.35 9.975,22.35 v1(9.725,22.6) 9.85,22.6 U1.F9@10.1,22.85 ; U1.F9@10.1,22.85 10.35,23.1 ; U1.F9@10.1,22.85 10.35,22.6 ; v1@10.35,22.1 U1.E8@10.6,22.35 ; 10.35,22.6 U1.F8@10.6,22.85 ; 10.35,22.6 U1.E8@10.6,22.35 ; 10.35,23.1 U1.G8@10.6,23.35 ; 10.35,23.1 U1.F8@10.6,22.85 ; 10.35,23.1 U1.G9@10.1,23.35 10.35,23.6 ; 10.35,23.6 U1.H8@10.6,23.85 ; 10.35,23.6 U1.G8@10.6,23.35 ; 10.35,23.6 U1.H9@10.1,23.85 10.35,24.1 ; 10.35,24.1 U1.H8@10.6,23.85 ; 10.35,24.1 U1.J9@10.1,24.35 10.1,24.475 v1(10.35,24.725) 10.6,24.475 U1.J8@10.6,24.35 ; 10.35,24.1 U1.J8@10.6,24.35 ; U1.E8@10.6,22.35 10.975,21.975 11.019,22.019 11.049,21.989 v1(11.121,21.989) ; U1.E8@10.6,22.35 10.85,22.6 ; U1.F8@10.6,22.85 10.85,23.1 ; U1.F8@10.6,22.85 10.85,22.6 ; U1.G8@10.6,23.35 10.85,23.6 ; U1.G8@10.6,23.35 10.85,23.1 ; U1.H8@10.6,23.85 10.85,24.1 ; U1.H8@10.6,23.85 10.85,23.6 ; U1.J8@10.6,24.35 10.85,24.1 ; 10.85,22.6 U1.F7@11.1,22.85 ; 10.85,22.6 U1.E7@11.1,22.35 ; 10.85,23.1 U1.G7@11.1,23.35 ; 10.85,23.1 U1.F7@11.1,22.85 ; 10.85,23.6 U1.H7@11.1,23.85 ; 10.85,23.6 U1.G7@11.1,23.35 ; 10.85,24.1 U1.J7@11.1,24.35 11.35,24.1 ; 10.85,24.1 U1.H7@11.1,23.85 ; U1.E7@11.1,22.35 11.35,22.6 ; U1.E7@11.1,22.35 11.121,22.329 v1(11.121,21.989) ; U1.F7@11.1,22.85 11.35,23.1 ; U1.F7@11.1,22.85 11.35,22.6 ; U1.G7@11.1,23.35 11.35,23.6 ; U1.G7@11.1,23.35 11.35,23.1 ; U1.H7@11.1,23.85 11.35,24.1 ; U1.H7@11.1,23.85 11.35,23.6 ; v1(11.121,21.989) 11.151,21.989 11.181,22.019 11.225,21.975 U1.E6@11.6,22.35 ; 11.35,22.6 U1.F6@11.6,22.85 ; 11.35,22.6 U1.E6@11.6,22.35 ; 11.35,23.1 U1.G6@11.6,23.35 ; 11.35,23.1 U1.F6@11.6,22.85 ; 11.35,23.6 U1.H6@11.6,23.85 ; 11.35,23.6 U1.G6@11.6,23.35 ; 11.35,24.1 U1.J6@11.6,24.35 ; 11.35,24.1 U1.H6@11.6,23.85 ; U1.E6@11.6,22.35 11.85,22.6 ; U1.F6@11.6,22.85 11.85,23.1 ; U1.F6@11.6,22.85 11.85,22.6 ; U1.G6@11.6,23.35 11.85,23.6 ; U1.G6@11.6,23.35 11.85,23.1 ; U1.H6@11.6,23.85 11.85,24.1 ; U1.H6@11.6,23.85 11.85,23.6 ; U1.J6@11.6,24.35 11.85,24.1 ; U1.J6@11.6,24.35 v1@11.85,24.6 ; U1.M6@11.6,25.85 U1.M5@12.1,25.85 ; U1.M6@11.6,25.85 U1.N6@11.6,26.35 11.6,26.55 11.863,26.813 v1(11.897,26.813) 11.897,26.753 12.1,26.55 U1.N5@12.1,26.35 U1.M5@12.1,25.85 ; U1.M6@11.6,25.85 U1.M7@11.1,25.85 11.1,25.6 11.446,25.254 11.489,25.298 v1(11.489,25.316) 11.489,25.272 11.507,25.254 11.6,25.347 U1.M6@11.6,25.85 ; 11.85,22.6 U1.F5@12.1,22.85 ; 11.85,23.1 U1.G5@12.1,23.35 ; 11.85,23.1 U1.F5@12.1,22.85 ; 11.85,23.6 U1.H5@12.1,23.85 ; 11.85,23.6 U1.G5@12.1,23.35 ; 11.85,24.1 U1.J5@12.1,24.35 v1@11.85,24.6 ; 11.85,24.1 U1.H5@12.1,23.85 ; U1.F5@12.1,22.85 12.475,23.225 12.515,23.185 12.471,23.142 v1(12.471,23.094) ; U1.G5@12.1,23.35 12.281,23.169 12.332,23.221 12.459,23.094 v1(12.471,23.094) ; U1.H5@12.1,23.85 12.551,23.399 12.471,23.32 12.515,23.277 12.471,23.233 v1(12.471,23.094) ; U1.M5@12.1,25.85 U1.M4@12.6,25.85 ; U1.M5@12.1,25.85 12.1,25.6 12.379,25.321 12.37,25.311 v1(12.37,25.177) 12.37,25.37 12.6,25.6 U1.M4@12.6,25.85 ; U1.M4@12.6,25.85 U1.M3@13.1,25.85 ; U1.M3@13.1,25.85 U1.M2@13.6,25.85 U1.L2@13.6,25.35 ; U1.M3@13.1,25.85 13.005,25.755 v1(13.005,25.304) 13.554,25.304 U1.L2@13.6,25.35
  Top Layer w0.254: v1@6.049,25.751 C208.2@6.569,25.751 ; SH100.1@9.165,12.295 SH100.1@9.756,12.295 ; SH100.1@14.293,11.992 14.199,12.086 SH100.1@14.407,12.295 ; v1(14.656,24.789) 14.75,24.695 14.75,24.7 15.3,24.7 X1.4@15.4,24.6 ; SH100.1@14.963,12.093 SH100.1@15.165,12.295
  Top Layer w0.305: v1(0.998,27.3) v1@0.998,27.35 ; v1(4.911,17.371) 4.989,17.371 C115.2@5.435,16.925 ; v1(5.159,20.128) C112.2@5.862,20.128 ; C115.2@5.36,16.925 5.368,16.917 5.967,16.917 6.528,17.478 v1(7.844,17.478) ; 5.9,19.171 C112.2@5.9,19.9 ; C112.2@5.9,20.089 5.9,20.003 C113.2@6.85,20.003 ; C113.2@6.889,20 C113.2@6.95,20 7.75,20 7.85,19.9 v1(7.85,19.896) ; v1(9.484,15.879) 9.484,15.957 9.442,15.999 9.502,16.058 9.657,15.903 9.786,16.032 9.807,16.01 9.83,16.033 9.772,16.091 9.791,16.109 9.8,16.1 9.75,16.05 C110.2@9.75,16.85 ; C111.2@9.7,18.25 9.75,18.2 9.677,18.127 v1@10.084,17.721 ; v1(10.084,17.659) 10.45,18.025 C116.2@10.45,18.038 ; v1(10.351,32.126) 10.351,32.775 ; 10.35,32.776 10.35,33.3 C10.2@11.05,33.3 11.05,34.106 11.385,34.441 12.024,34.441 C6.2@12.024,34.676 ; C2.1@10.4,31.7 v1@10.95,31.15 ; C116.2@10.45,18.25 C116.2@10.45,18.038 ; v1(10.95,30.2) v1@10.95,30.15 ; v1@10.95,30.214 v1@10.95,30.15 ; v1(10.951,31.226) 10.874,31.226 v1@10.95,31.15 ; C117.2@11.2,18.25 C117.2@11.2,18.017 ; C117.2@11.202,18.019 C117.2@11.2,18.017 ; v1(11.897,26.813) 11.897,27.003 11.563,27.337 v1(11.563,27.34) 11.56,27.34 11.375,27.525 v1(11.375,27.975) 11.15,28.2 11.15,28.72 10.95,28.92 v1(10.95,29.278) v1@10.95,30.15 ; v1(12.245,35.092) 12.245,34.645 C6.2@12.15,34.55 12.278,34.422 16.012,34.422 16.563,34.973 16.474,35.061 v1(15.81,35.061) ; v1@13.511,16.177 C124.2@13.511,16.791 ; BAL1.5@13.675,32.15 14.502,32.15 14.478,32.126 v1(14.426,32.126) ; v1@15.228,32.095 15.1,32.223 C7.2@15.1,32.75 15.8,32.75 15.8,32.28 v1@15.873,32.206 ; C102.2@15.95,22.45 C102.2@15.95,22.5 ; C207.2@16.368,26.857 16.404,26.82 v1(17.183,26.82) ; 16.422,20.433 16.161,20.694 C114.2@16.161,20.972 16.711,20.972 17.249,20.433 17.504,20.433 17.876,20.805 v1(17.876,21.626) ; X1.2@16.743,25.953 16.898,26.108 v1(17.336,26.108) ; v1@17.16,32.117 17.231,32.187 v1(17.145,32.187) 17.145,32.771 17.665,32.771 C8.2@17.717,32.718 ; v1@17.927,32.219 v1(17.958,32.187) v1@18.02,32.187 ; v1@17.952,32.086 v1@17.983,32.117 ; v1@17.972,32.216 17.936,32.216 17.8,32.352 17.8,32.65 C8.2@17.7,32.75 19.095,32.75 v1@19.804,32.04 ; SH100.1@28,36.95 v1(28,37) ; C116.2@10.45,18.038 v1(10.833,17.654) 10.837,17.654 C117.2@11.2,18.017 ; v1@10.95,30.15 v1@10.95,31.15
  Top Layer w0.457: C114.2@16.135,20.972 v1(16.135,21.997)
  Top Layer w0.508: v1(6.773,28.107) C106.2@7.343,28.107 7.343,28.435 ; v1(8.775,29.327) 8.85,29.4 v1@8.95,29.3 ; v1(9.05,28.45) 9.175,28.325 C107.2@9.6,28.325 ; C1.1@9.35,29.1 C1.1@9.325,29.125 ; v1@8.95,29.3 9.15,29.3 C1.1@9.325,29.125 ; v1@8.95,29.3 v1(9.325,29.675) 9.325,29.15 9.35,29.125 C1.1@9.325,29.125
  Top Layer w0.635: v1(2,40.25) 1.475,40.25 ; v1@2.198,33.95 P2.2@4.225,33.95 4.805,33.95 5.486,34.632 v1(5.486,34.931) ; 2.51,30.95 P2.3@4.225,30.95 v1(5.65,30.95) ; 1.475,40.25 1.475,41.113 AT1.2@1.298,41.29 1.1,41.092 v1(1.1,40.25) 1.475,40.25
  Top Layer w1: SH100.1@1.994,19.464 1.994,12.297 SH100.1@1.996,12.296 ; SH100.1@2.006,38.305 v1(1.996,38.294) v1(4.05,38.294) ; SH100.1@2.3,12.6 SH100.1@1.996,12.296 ; v1(8.2,38.3) 8.205,38.305 SH100.1@9.165,38.305 SH100.1@10.445,38.305 ; SH100.1@9.165,12.295 SH100.1@1.996,12.296 ; SH100.1@9.756,12.295 13.11,12.295 13.158,12.344 14.359,12.344 14.407,12.295 SH100.1@15.165,12.295 SH100.1@21.02,12.295 ; v1(10.45,38.3) SH100.1@10.445,38.305 ; v1(13.95,38.3) SH100.1@13.955,38.305 ; SH100.1@19.324,38.3 15.17,38.3 SH100.1@15.165,38.305 SH100.1@13.955,38.305 ; SH100.1@19.428,38.3 21.16,38.3 v1(21.165,38.305) SH100.1@21.176,38.294 ; SH100.1@21.165,12.295 SH100.1@27.994,12.295 ; SH100.1@25.8,38.3 25.805,38.294 v1(27.25,38.294) SH100.1@27.994,38.294 ; SH100.1@27.994,12.296 27.994,31.454 SH100.1@28.005,31.465 ; SH100.1@10.445,38.305 SH100.1@13.955,38.305
  Signal Layer 2 w0.305: v1(14.426,32.126) 14.478,32.126 14.502,32.15 v1@14.527,32.125
  Bottom Layer w0.254: C205.2@4.388,15.413 4.913,15.413 C205.2@4.938,15.438 ; v1(23.66,30.112) 23.905,29.867 U200.3@23.905,29.35 ; TP1.2@23.845,37.985 TP1.2@23.854,37.976 ; 23.967,37.592 23.967,37.863 TP1.2@23.9,37.93 ; U200.4@24.392,29.35 25.2,29.35 25.2,30.047 v1(25.205,30.051) ; TP1.2@23.854,37.976 TP1.2@23.9,37.93 ; TP1.2@23.854,37.976 23.854,37.421 23.9,37.375 TP1.2@23.9,37.93
  Bottom Layer w0.305: 3.594,13.495 3.594,13.668 C201.2@3.85,13.925 ; U200.2@23.392,29.351 23.392,29.844 v1(23.66,30.112) ; TPJ13.1@24.6,19.2 24.6,19.016 24.813,19.229 v1(24.813,20.018) ; 24.995,39.135 25.16,39.3 v1(25.725,39.3)
  Bottom Layer w0.508: C201.2@3.85,14.012 v1(4.438,14.012) ; C203.2@3.85,14.732 4.439,14.732 v1(4.445,14.726)
  Bottom Layer w0.635: P201.1@2.9,9.25 2.95,9.2 2.25,9.2 2.25,9.8 2.685,9.8 P201.1@2.935,9.55 ; P200.2@2.935,36.45 2.935,38.935 v1(3.25,39.25) ; v1(4.083,15.86) 4.094,15.86 4.101,15.854 4.859,15.854 C205.2@4.859,15.708 ; C205.2@4.7,15.875 C205.2@4.7,16.013 ; v1(25.8,35.05) 25.8,36.445 P200.38@25.795,36.45 25.795,38.29 v1(25.825,38.319) ; P201.39@27.065,9.55 27.165,9.65 v1(27.8,9.65) ; P201.39@27.065,9.55 27.7,9.55 v1(27.8,9.65) ; P201.39@27.065,9.55 27.065,9.035 27.15,8.95 27.2,9 v1(27.8,9) v1(27.8,9.65)
  other v1: 1.025,8.875 28.95,8.875 2.25,9.171 28.948,9.6 0.998,9.8 2.25,9.821 21.366,10.917 20.111,10.972 23.756,10.992 25.099,10.982 3,11 8.418,10.999 10.551,10.999 14.748,11.017 16.171,10.994 22.424,10.995 26.5,11 0.998,12.25 28.948,12.4 28.948,13.7 16.38,13.751 15.412,13.814 0.998,13.85 26.5,14 8.541,14.463 9.802,14.448 19.836,14.849 28.948,14.85 21.5,15.25 0.998,15.3 28.948,15.9 11.463,15.943 13.624,15.982 26.5,16.25 0.998,16.9 28.948,16.9 18.534,17.003 28.948,18.05 17.347,18.162 0.998,18.25 26.5,18.25 13.052,19.094 28.948,19.15 0.998,19.55 28.948,20.25 1.002,20.711 28.948,21.25 18.75,21.5 19.809,21.503 22,21.5 24.75,21.5 15.476,22.101 28.948,22.35 17.746,22.686 18.748,22.686 19.815,22.692 21.869,22.681 4.83,23.221 28.948,23.4 1,23.75 26.5,23.75 18.501,24.171 28.948,24.45 4.806,25.254 1,25.5 28.948,25.55 3.323,25.803 4.806,26.447 28.948,26.6 28.948,27.7 3.419,27.822 15.4,28.242 0.998,28.55 4.187,28.604 28.948,28.8 15.404,29.07 0.998,29.8 16.778,29.921 28.948,29.95 6.388,29.983 2.737,30.185 0.998,31 28.948,31.05 6.7,31.2 7.75,31.2 8.6,31.2 21.343,32.016 25,32 19.793,32.06 15.301,32.108 0.998,32.15 15.884,32.187 28.948,32.2 0.998,33.5 28.948,33.55 2.149,33.999 27.8,34.1 11.228,34.799 13.465,34.903 6.8,35 16.859,35.009 18.082,35.012 19.375,35 20.7,35 21.95,35 24.7,35 27.05,35 8.669,35.237 29,36.4 1,36.45 1,37.4 29,37.4 1,38.25 12.15,38.3 19.376,38.352 29,38.35 1,39.2 2,39.25 4.55,39.25 7.1,39.25 8.2,39.25 9.325,39.25 10.45,39.25 11.55,39.25 12.75,39.25 13.825,39.25 14.95,39.25 15.875,39.25 16.95,39.25 17.95,39.25 19.05,39.25 20.05,39.25 21.025,39.25 21.95,39.275 26.6,39.3 27.5,39.3 28.3,39.3 29,39.3 21.4,40.225 22.35,40.225 2.825,40.233 3.9,40.233 6.55,40.233 7.6,40.233 8.725,40.233 9.825,40.233 10.975,40.233 12.15,40.233 13.2,40.233 14.375,40.233 15.4,40.233 16.35,40.233 17.375,40.233 18.475,40.233 19.475,40.233 20.475,40.233 26.15,40.25 27.05,40.25 27.85,40.25 28.65,40.25
NetAT1_1: AT1.1 R1.2 | length 9.5
  Top Layer w0.457: AT1.1@5.184,41.29 5.184,40.54 ccw(c6.752,40.54) 5.643,39.432 5.705,39.37 cw(c4.51,38.175) 6.2,38.175 6.2,37.447 ; 6.176,37.447 ccw(c8.028,37.447) 6.719,36.138 7.4,35.456 R1.2@9.5,33.356
NetBAL1_1: BAL1.1 C6.1 L6.2 | length 1.7
  Top Layer w0.203: C6.1@12.125,33.55 C6.1@12.15,33.575
  Top Layer w0.396: BAL1.1@12.024,32.8 12.125,32.901 C6.1@12.125,33.55 ; C6.1@12.15,33.65 L6.2@13.025,33.65
NetBAL1_3: BAL1.3 C5.2 L4.1 | length 2.3
  Top Layer w0.203: L4.1@11.7,30.075 12.025,30.4 12.25,30.4 C5.2@12.4,30.55 12.4,31.475 12.425,31.5 BAL1.3@12.024,31.5
NetBAL1_4: BAL1.4 C5.1 L3.1 | length 2.2
  Top Layer w0.203: BAL1.4@13.675,31.5 13.3,31.5 C5.1@13.3,30.55 13.425,30.425 13.675,30.425 14,30.1 L3.1@14,30.075
NetC1_2: C1.2 L1.2 L2.1 | length 1.7
  Top Layer w0.396: C1.2@10.15,29.125 L2.1@10.15,29.875 ; C1.2@10.25,29.1 10.35,29 10.35,28.625 L1.2@10.575,28.4 ; C1.2@10.25,29.125 C1.2@10.329,29.046
NetC2_2: C2.2 L2.2 R1.1 R2.1 | length 1.9
  Top Layer w0.396: R2.1@9.5,32.5 9.5,31.7 9.5,31.5 10.075,30.925 L2.2@10.15,30.925
NetC3_1: C3.1 L3.2 U1.N1 | length 5.4
  Top Layer w0.203: v1(13.25,29.9) C3.1@13.25,29.325 13.45,29.125 13.9,29.125 L3.2@14,29.025 ; U1.N1@14.1,26.35 14.1,26.975 v1(14.4,27.275)
  PWR Layer 4 w0.203: v1(13.25,29.9) v1(14.4,27.275)
NetC3_2: C3.2 L5.2 U1.N3 | length 2.4
  Top Layer w0.127: U1.N3@13.1,26.35 12.979,26.471 12.979,27.254 L5.2@13.375,27.65 ; C3.2@13.25,28.425 13.25,27.825 13.425,27.65 L5.2@13.4,27.625
NetC4_1: C4.1 L4.2 U1.N2 | length 5.2
  Top Layer w0.203: L4.2@11.7,29.025 11.8,29.125 12.275,29.125 C4.1@12.475,29.325 v1(12.475,29.9) ; U1.N2@13.6,26.35 v1(13.6,27)
  PWR Layer 4 w0.203: v1(12.475,29.9) v1(13.6,27)
NetC4_2: C4.2 L5.1 U1.N4 | length 2.4
  Top Layer w0.127: L5.1@12.325,27.65 12.75,27.225 12.75,26.5 U1.N4@12.6,26.35 ; L5.1@12.375,27.65 12.475,27.75 C4.2@12.475,28.425
NetC7_1: C7.1 L6.1 L7.2 | length 1.8
  Top Layer w0.396: L6.1@14.075,33.65 C7.1@15.1,33.65 L7.2@15.875,33.65
NetC8_1: C8.1 L7.1 P1.1 TP1.1 | length 17.6
  Top Layer w0.457: L7.1@16.925,33.65 C8.1@17.7,33.65 17.758,33.708 21.742,33.708 ccw(c21.772,35.78) 23.845,35.75 v1(23.845,39.135) 24.856,40.146 ccw(c23.06,41.942) 25.6,41.942 P1.1@25.6,44.6
NetC102_1: C102.1 C103.1 L102.2 U1.J1 U1.J2 | length 4
  Top Layer w0.254: U1.J2@13.6,24.35 U1.J1@14.1,24.35 14.233,24.217 14.361,24.217 14.5,24.217 14.576,24.217 14.862,23.932 14.862,23.845 15.2,23.507 C103.1@15.2,23.4
  Top Layer w0.305: C103.1@15.2,23.4 16.7,23.4 L102.2@16.95,23.15
NetC112_1: C112.1 C113.1 R100.2 U1.B13 | length 3.5
  Top Layer w0.254: C113.1@7,20.85 7.268,20.582 7.825,20.582 8.093,20.85 U1.B13@8.1,20.85
  Top Layer w0.381: C112.1@5.9,21.3 6.179,21.021 6.95,21.021 C113.1@6.95,20.9 C113.1@7,20.85
  Top Layer w0.508: R100.2@5.257,20.976 5.576,20.976 C112.1@5.9,21.3
NetC117_1: C117.1 U1.A9 | length 1.8
  Top Layer w0.203: U1.A9@10.1,20.25 U1.A9@10.1,20.268 ; U1.A9@10.1,20.35 U1.A9@10.1,20.268 ; 10.278,20.09 U1.A9@10.1,20.268
  Top Layer w0.305: 10.278,20.09 10.506,19.862 10.638,19.862 11.2,19.3 C117.1@11.2,19.15
NetL1_1: L1.1 U1.N7 | length 1.2
  Top Layer w0.203: U1.N7@11.1,26.35 11.1,26.725
  Top Layer w0.396: L1.1@10.575,27.35 11.029,26.896 cw(c10.859,26.725) 11.1,26.725
NetL100_1: L100.1 U1.A12 | length 2.3
  Top Layer w0.203: 8.6,19.95 U1.A12@8.6,20.35
  Top Layer w0.254: L100.1@7.6,18.85 8.2,18.85 L100.1@8.6,19.25
  Top Layer w0.635: L100.1@8.6,19.25 8.6,19.95
NetL101_2: L101.2 R100.1 | length 0.9
  Top Layer w0.508: L101.2@3.285,20.841 3.372,20.928 R100.1@4.1,20.928
NetP2_1: P2.1 R2.2 | length 2.8
  Top Layer w0.396: P2.1@5.825,32.45 P2.1@5.85,32.475
  Top Layer w0.4: P2.1@5.85,32.475 R2.2@8.6,32.475
NetU1_K1: U1.K1 X1.1 | length 3.1
  Top Layer w0.102: U1.K1@14.1,24.85 14.1,24.917 14.379,25.196 15.948,25.196 X1.1@16.667,24.477 ; X1.1@16.45,24.55 X1.1@16.5,24.5
NetU1_L1: U1.L1 X1.3 | length 2
  Top Layer w0.102: U1.L1@14.1,25.35 14.14,25.31 14.206,25.31 14.373,25.477 15.433,25.477 15.567,25.611 X1.3@15.567,25.877 ; X1.3@15.4,25.877 X1.3@15.4,26
PAVDD: L103.1 R210.1 R211.1 | length 13.6
  Top Layer w0.635: v1(5.054,28.417) 5.05,28.421 v1(5.05,29.075) 5.075,29.1 6.475,29.1 L103.1@6.5,29.125
  PWR Layer 4 w0.635: v1@4.424,19.552 4.124,19.853 4.124,27.129 5.054,28.059 v1(5.054,28.417) 5.05,28.421 v1(5.05,29.075) v1@5.055,29.07
  Bottom Layer w0.635: v1(4.093,20.007) 4.093,19.847 4.501,19.439 4.506,19.444 4.461,19.489 v1(4.461,19.501) 4.482,19.501 4.658,19.324 R210.1@4.658,18.966
RADIO_PA0: P200.19 P201.36 TPJ5.1 U1.M13 | length 60.7
  Top Layer w0.102: v1@7.136,25.85 U1.M13@8.1,25.85
  Signal Layer 5 w0.102: v1(7.188,25.787) 7.188,25.312 7.541,24.96 7.903,24.96 8.679,25.736 10.261,25.736 10.499,25.498 10.499,25.161 10.495,25.157 10.495,25.155 10.756,24.893 10.756,24.608 11.433,23.931 14.946,23.931 16.24,25.224 16.24,28.367 16.658,28.785 v1(16.945,28.785) 17.003,28.727 18.379,28.727 18.703,28.403 21.478,28.403 v1@21.925,27.955 ; v1(14.901,35.04) 15.347,34.594 20.351,34.594 22.96,31.984 v1(23.546,31.984)
  Bottom Layer w0.102: P200.19@14.365,33.749 14.365,34.132 14.69,34.458 14.69,34.94 14.79,35.04 v1(14.901,35.04) ; TPJ5.1@15.55,25.7 15.626,25.776 15.626,26.829 15.872,27.075 16.823,27.075 17.142,27.394 17.142,28.588 v1(16.945,28.785) ; 21.742,27.506 21.742,25.374 22.879,24.238 23.307,24.238 23.952,23.593 23.952,19.475 23.948,19.47 23.948,18.93 24.435,18.443 24.435,16.218 23.578,15.361 23.578,14.329 24.212,13.695 24.212,12.763 P201.36@24.525,12.45 ; 21.748,27.506 21.956,27.714 v1(21.956,27.982) ; v1@22.012,27.943 21.742,28.213 21.742,30.567 23.16,31.984 v1(23.546,31.984)
RADIO_PA1: P200.20 P201.37 TPJ6.1 U1.L13 | length 57.6
  Top Layer w0.102: v1(7.696,25.38) 8.02,25.38 8.075,25.325 U1.L13@8.1,25.35
  Signal Layer 5 w0.102: v1(7.696,25.38) 7.755,25.38 8.314,25.939 10.345,25.939 10.702,25.582 10.702,25.235 10.96,24.978 10.96,24.692 11.518,24.134 14.862,24.134 16.037,25.308 16.037,28.451 16.777,29.191 17.261,29.191 17.51,28.941 v1(18.794,28.941) 18.794,29.041 18.821,29.068 19.284,28.606 22.352,28.606 v1(22.428,28.682) ; v1(14.25,35) 14.25,34.82 14.679,34.39 20.267,34.39 22.221,32.437 22.221,30.911 22.469,30.663 v1(22.479,30.663)
  Bottom Layer w0.102: v1(14.25,35) 14.25,36.335 P200.20@14.365,36.45 ; v1(18.794,28.941) 18.794,28.296 TPJ6.1@19.02,28.07 ; v1@22.427,28.682 22.427,29.692 22.594,29.859 22.594,30.674 v1@22.475,30.556 ; v1(22.479,30.663) 22.479,30.622 v1@22.51,30.591 ; v1@22.588,28.523 22.588,27.74 22.149,27.301 22.149,25.543 23.047,24.644 23.475,24.644 24.391,23.728 24.391,22.759 25.273,21.878 25.273,13.532 ; 25.273,13.532 25.273,11.406 25.795,10.883 P201.37@25.795,9.55
RADIO_PA2: P200.21 P201.38 TPJ7.1 U1.L12 | length 39.5
  Top Layer w0.102: U1.L12@8.6,25.35 8.87,25.35 v1(9.115,25.104)
  Signal Layer 5 w0.102: v1(9.115,25.104) 9.115,24.81 9.607,24.319 10.758,24.319 11.349,23.727 15.031,23.727 16.443,25.14 16.443,25.432 ; v1@16.693,27.582 v1(16.693,27.519) 16.443,27.269 16.443,25.432 ; v1(23.149,25.139) 22.95,25.139 22.619,25.47 16.482,25.47 16.443,25.432
  Bottom Layer w0.102: P200.21@15.635,33.55 15.635,32.7 15.735,32.601 16.097,32.601 16.303,32.395 16.303,31.666 15.951,31.314 15.951,30.971 16.252,30.67 16.252,30.13 16.041,29.918 16.041,28.479 TPJ7.1@16.49,28.03 TPJ7.1@16.789,28.329 ; v1(23.149,25.139) 23.441,24.848 23.559,24.848 24.594,23.813 24.594,22.896 25.476,22.014 25.476,13.075 25.489,13.062 25.489,12.756 25.507,12.756 25.626,12.637 25.626,12.619 P201.38@25.795,12.45
RADIO_PA3: P200.3 P200.22 TPJ8.1 U1.K13 | length 35.7
  Top Layer w0.102: v1@6.95,24.85 U1.K13@8.1,24.85
  Signal Layer 2 w0.102: v1(2.888,25.326) 2.968,25.326 3.523,24.771 6.604,24.771 6.807,24.974 v1(6.934,24.974)
  Signal Layer 5 w0.102: v1(4.612,34.97) 4.872,34.97 5.318,34.524 9.747,34.524 10.601,33.67 12.006,33.67 12.708,32.968 14.518,32.968 14.832,32.654 14.832,32.323 14.832,32.295 14.832,31.723 v1@15.308,31.248 ; v1(15.215,31.248) v1@15.308,31.248 ; v1@15.355,31.295 v1@15.308,31.248
  Bottom Layer w0.102: v1(2.888,25.326) 2.662,25.552 2.662,26.238 2.034,26.866 2.034,30.515 3.864,32.344 3.864,32.573 4.205,32.915 P200.3@4.205,33.55 4.205,34.225 4.612,34.632 v1(4.612,34.97) ; TPJ8.1@15.6,30.4 15.215,30.785 v1(15.215,31.248) 15.293,31.248 14.887,31.653 14.887,32.298 15.041,32.451 15.041,34.522 15.316,34.797 15.316,35.497 P200.22@15.635,35.817
RADIO_PA4: R103.2 U1.K12 U100.A3 | length 17.9
  Top Layer w0.102: v1(11.876,17.526) 12.467,17.526 12.808,17.866 13.603,17.866 U100.A3@13.608,17.871
  Signal Layer 2 w0.102: v1(5.461,25.202) 6.461,25.202 6.639,25.38 7.103,25.38 7.523,24.96 8.49,24.96 v2(8.6,24.85)
  Signal Layer 5 w0.102: 5.486,24.948 5.486,24.471 5.994,23.963 5.994,21.418 6.881,20.532 11.214,20.532 11.619,20.126 11.619,18.284 11.876,18.027 v1(11.876,17.526)
RADIO_PA5: P200.18 U1.J13 | length 27.5
  Top Layer w0.102: v1@7.763,24.348 7.765,24.35 U1.J13@8.1,24.35 U1.J13@8.082,24.332
  Signal Layer 2 w0.102: v1(2.851,24.513) 2.851,24.523 3.009,24.364 v1@7.686,24.364
  Signal Layer 5 w0.102: v1(3.988,35.083) 3.988,35.131 4.367,35.51 6.312,35.51 6.853,36.051 11.549,36.051 12.041,35.559 12.041,35.51 13.439,35.51 v1(13.584,35.655)
  Bottom Layer w0.102: v1(2.851,24.513) 2.459,24.904 2.459,26.154 1.831,26.782 1.831,30.599 3.661,32.429 3.661,34.756 v1(3.988,35.083)
  other v1: 7.736,24.346
RADIO_PA6: P201.4 U1.J12 | length 24
  Signal Layer 2 w0.102: v1(1.503,22.967) 2.263,23.728 2.263,24.548 2.635,24.919 2.72,24.919 3.037,24.919 3.389,24.567 7.128,24.567 7.317,24.756 8.194,24.756 v2(8.6,24.35)
  Signal Layer 5 w0.102: v1@1.439,22.796 1.231,22.589 1.231,21.486 1.627,21.09 1.627,13.661 3.883,11.406 4.278,11.406 4.531,11.154 v1(4.531,10.906)
  Bottom Layer w0.102: P201.4@4.205,12.45 4.531,12.124 v1(4.531,10.906)
RADIO_PA7: P201.6 U1.J11 | length 26
  Top Layer w0.102: U1.J11@9.1,24.35 9.55,24.8 v1(9.7,24.8)
  Signal Layer 5 w0.102: v1@5.059,13.585 6.938,11.705 7.354,11.705 7.522,11.537 11.252,11.537 v1(11.786,11.004)
  Bottom Layer w0.102: v1(5.175,13.701) 5.175,13.314 5.475,13.014 P201.6@5.475,12.45 ; v1(9.7,24.8) 9.475,24.8 8.522,23.847 8.522,22.079 8.866,21.734 8.866,19.475 8.572,19.18 8.572,18.294 8.593,18.273 10.841,16.024 10.841,14.631 11.303,14.17 11.303,13.612 11.303,11.43 11.729,11.004 v1(11.786,11.004)
RADIO_PA8: P201.8 U1.H13 | length 13.5
  Top Layer w0.102: v1(7.112,23.755) 7.207,23.85 v1@7.237,23.85 ; v1@7.237,23.818 7.269,23.85 U1.H13@8.1,23.85
  Bottom Layer w0.102: P201.8@6.745,12.45 6.939,12.644 6.833,12.749 6.833,13.992 6.939,14.097 6.939,20.338 6.939,20.848 6.195,21.592 6.195,23.412 6.461,23.678 7.036,23.678 v1(7.112,23.755)
RADIO_PA9: P201.10 U1.H12 | length 23.6
  Signal Layer 2 w0.102: v1@2.892,23.882 3.028,23.882 3.307,24.161 7.311,24.161 7.547,23.925 7.883,23.925 8.525,23.925 v2(8.6,23.85)
  Signal Layer 5 w0.102: v1(2.866,23.903) 2.866,23.836 4.078,22.625 4.078,21.145 3.456,20.522 3.456,14.419 4.64,13.234 5.122,13.234 6.854,11.502 7.27,11.502 v1(7.76,11.012)
  Bottom Layer w0.102: v1(7.76,11.012) 7.76,11.862 8.181,12.284 P201.10@8.015,12.45
RADIO_PB6: P201.12 U1.F12 | length 25.4
  Signal Layer 2 w0.102: v1(3.066,22.303) 3.077,22.292 3.355,22.292 3.911,21.736 6.092,21.736 6.667,21.161 7.133,21.161 7.264,21.292 7.264,21.434 7.502,21.672 7.644,21.672 8.228,22.256 8.228,22.427 8.6,22.799 v2(8.6,22.85)
  Signal Layer 5 w0.102: v1(3.066,22.303) 3.469,21.9 3.469,21.397 2.846,20.775 2.846,14.166 4.388,12.625 4.832,12.625 6.032,11.424 6.032,11.17 6.886,10.316 8.916,10.316 9.574,10.974 v1(9.725,10.974)
  Bottom Layer w0.102: P201.12@9.285,11.809 9.725,11.369 v1(9.725,10.974)
RADIO_PB7: P201.14 U1.E13 | length 12.6
  Top Layer w0.102: v1(7.518,22.408) 7.508,22.408 7.473,22.443 7.54,22.51 7.7,22.35 U1.E13@8.1,22.35
  Bottom Layer w0.102: v1(7.518,22.408) 7.518,22.459 7.912,22.065 7.912,21.755 8.257,21.41 8.257,19.727 7.962,19.432 7.962,18.041 7.983,18.02 10.231,15.772 10.231,13.308 10.555,12.985 P201.14@10.555,12.45 10.389,12.284 P201.14@10.404,12.268
RADIO_PB8: P201.17 U1.E12 | length 28.8
  Signal Layer 2 w0.102: v1(3.062,21.662) 2.933,21.533 6.008,21.533 6.682,20.859 7.839,20.859 8.079,21.099 8.079,21.82 8.6,22.341 v2(8.6,22.35)
  Signal Layer 5 w0.102: v1(3.062,21.662) 3.062,21.278 2.643,20.859 2.643,14.082 4.304,12.422 4.747,12.422 5.829,11.34 5.829,11.086 6.81,10.105 12.328,10.105 12.874,10.65 v1(12.874,10.901)
  Bottom Layer w0.102: v1@12.856,10.869 12.856,10.229 13.095,9.99 P201.17@13.095,9.55
RADIO_PB9: P201.18 U1.D13 | length 18.4
  Top Layer w0.102: v1(6.835,21.568) 6.835,21.573 7.112,21.85 U1.D13@8.1,21.85
  GND Layer 3 w0.102: v1(6.835,21.568) 6.85,21.582 v1@6.85,21.6
  Signal Layer 5 w0.102: v1(7.285,13.747) 7.285,13.783 7.731,14.23 8.161,14.23 8.364,14.026 10.296,14.026 10.703,14.433 11.04,14.433 11.26,14.212 11.947,14.212 12.494,13.665 v1(12.979,13.665)
  Bottom Layer w0.102: v1(6.835,21.568) 6.835,21.239 7.142,20.932 7.142,14.281 7.285,14.138 v1(7.285,13.747) ; v1(12.979,13.665) 13.095,13.55 P201.18@13.095,12.474 ; v1@13.122,13.665 13.122,12.501 P201.18@13.095,12.474 ; P201.18@13.095,12.474 13.083,12.462 P201.18@13.095,12.45 P201.18@13.095,12.474
RADIO_PB10: P200.4 U1.D12 | length 24
  Top Layer w0.102: U1.D12@8.492,21.85 v2(8.6,21.85)
  Signal Layer 2 w0.102: v1(1.843,21.75) 2.145,21.75 2.639,21.255 3.383,21.255 3.457,21.33 5.924,21.33 6.598,20.656 7.923,20.656 8.283,21.015 8.283,21.532 v2(8.6,21.85)
  Bottom Layer w0.102: v1(1.843,21.75) 2.256,22.163 2.256,26.07 1.615,26.711 1.615,30.67 3.457,32.513 3.457,35.138 4.205,35.885 P200.4@4.205,36.034
RADIO_PB11: P200.34 U1.D11 | length 41
  Top Layer w0.102: U1.D11@9.1,21.85 9.15,21.9 9.131,21.919 v1(9.131,22.331)
  Signal Layer 2 w0.102: v1(9.131,22.331) 9.131,21.106 9.716,20.522 10.141,20.522 10.998,19.664 10.998,18.403 11.469,17.932 11.469,17.358 11.707,17.119 14.224,17.119 15.247,16.097 20.088,16.097 20.279,15.905 21.085,15.905 21.342,16.162 22.305,16.162 22.746,16.604 23.229,16.604 v1(23.292,16.541)
  Bottom Layer w0.102: P200.34@23.255,36.45 23.255,35.771 23.227,35.771 22.711,35.255 22.711,32.109 21.336,30.735 21.336,25.206 22.479,24.063 22.479,22.454 22.932,22.001 22.932,17.426 23.292,17.066 v1(23.292,16.541)
RADIO_PB12: P200.33 U1.C13 | length 35.9
  Top Layer w0.102: v1(7.671,21.265) 7.755,21.35 U1.C13@8.1,21.35
  Signal Layer 5 w0.102: v1(7.671,21.265) 7.977,20.959 11.361,20.959 12.02,20.3 13.844,20.3 14.334,19.811 17.48,19.811 18.105,20.435 20.042,20.435 21.712,18.765 21.712,17.965 21.98,17.698 23.171,17.698 v1(23.406,17.933)
  Bottom Layer w0.102: P200.33@23.255,33.55 23.255,32.949 22.914,32.608 22.914,32.025 21.539,30.651 21.539,25.29 22.682,24.147 22.682,22.538 23.135,22.085 23.135,18.205 v1(23.406,17.933)
RADIO_PB13: P200.32 U1.C12 | length 39.7
  Signal Layer 2 w0.102: v2(8.6,21.35) 9.632,20.318 10.057,20.318 10.795,19.58 10.795,18.319 11.266,17.848 11.266,17.236 11.586,16.916 14.14,16.916 15.163,15.893 20.003,15.893 20.195,15.702 21.169,15.702 21.427,15.959 22.735,15.959 v1(22.86,16.084)
  Bottom Layer w0.102: P200.32@21.985,36.45 21.985,35.741 22.507,35.219 22.507,32.194 21.133,30.819 21.133,25.122 22.276,23.979 22.276,22.37 22.728,21.917 22.728,16.263 v1@22.86,16.131
RADIO_PB14: U1.C11 X2.2 | length 5.9
  Top Layer w0.127: X2.2@5.692,23.95 X2.2@5.8,23.95 ; X2.2@5.692,23.974 5.928,23.974 v1(6.629,23.272) ; U1.C11@9.1,21.35 v1(9.6,21.85)
  Signal Layer 5 w0.127: v1(6.629,23.272) 6.629,22.959 7.099,22.489 7.099,22.235 7.145,22.189 7.345,21.989 7.977,21.989 8.116,21.85 v1(9.6,21.85)
RADIO_PB15: U1.C10 X2.1 | length 5.8
  Top Layer w0.127: X2.1@5.141,22.455 5.144,22.459 5.221,22.383 X2.1@5.692,22.383 ; X2.1@5.692,22.474 6.513,22.474 v1(6.604,22.383) ; U1.C10@9.6,21.35 9.65,21.4 9.669,21.381 v1(10.081,21.381)
  Signal Layer 5 w0.127: v1@6.794,22.216 7.25,21.761 7.882,21.761 8.021,21.621 9.08,21.621 9.271,21.431 10.131,21.431 v1(10.081,21.381)
RADIO_PC0: T2.1 U1.A5 | length 22.6
  Top Layer w0.102: U1.A5@12.1,20.35 12.393,20.057 12.606,20.057 13.111,19.551 13.236,19.551 13.386,19.401 14.883,19.401 15.769,18.515 15.769,17.307 15.808,17.346 15.826,17.328 15.801,17.303 v1@15.915,17.189 ; v1(15.826,17.201) v1@15.903,17.201
  Signal Layer 2 w0.102: v1(6.11,7.72) 6.11,11.167 7.623,12.679 12.933,12.679 13.743,13.488 v1(13.743,14.131)
  Signal Layer 5 w0.102: v1(13.743,14.131) 13.743,14.684 15.533,16.474 15.533,16.958 15.776,17.201 v1(15.826,17.201)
